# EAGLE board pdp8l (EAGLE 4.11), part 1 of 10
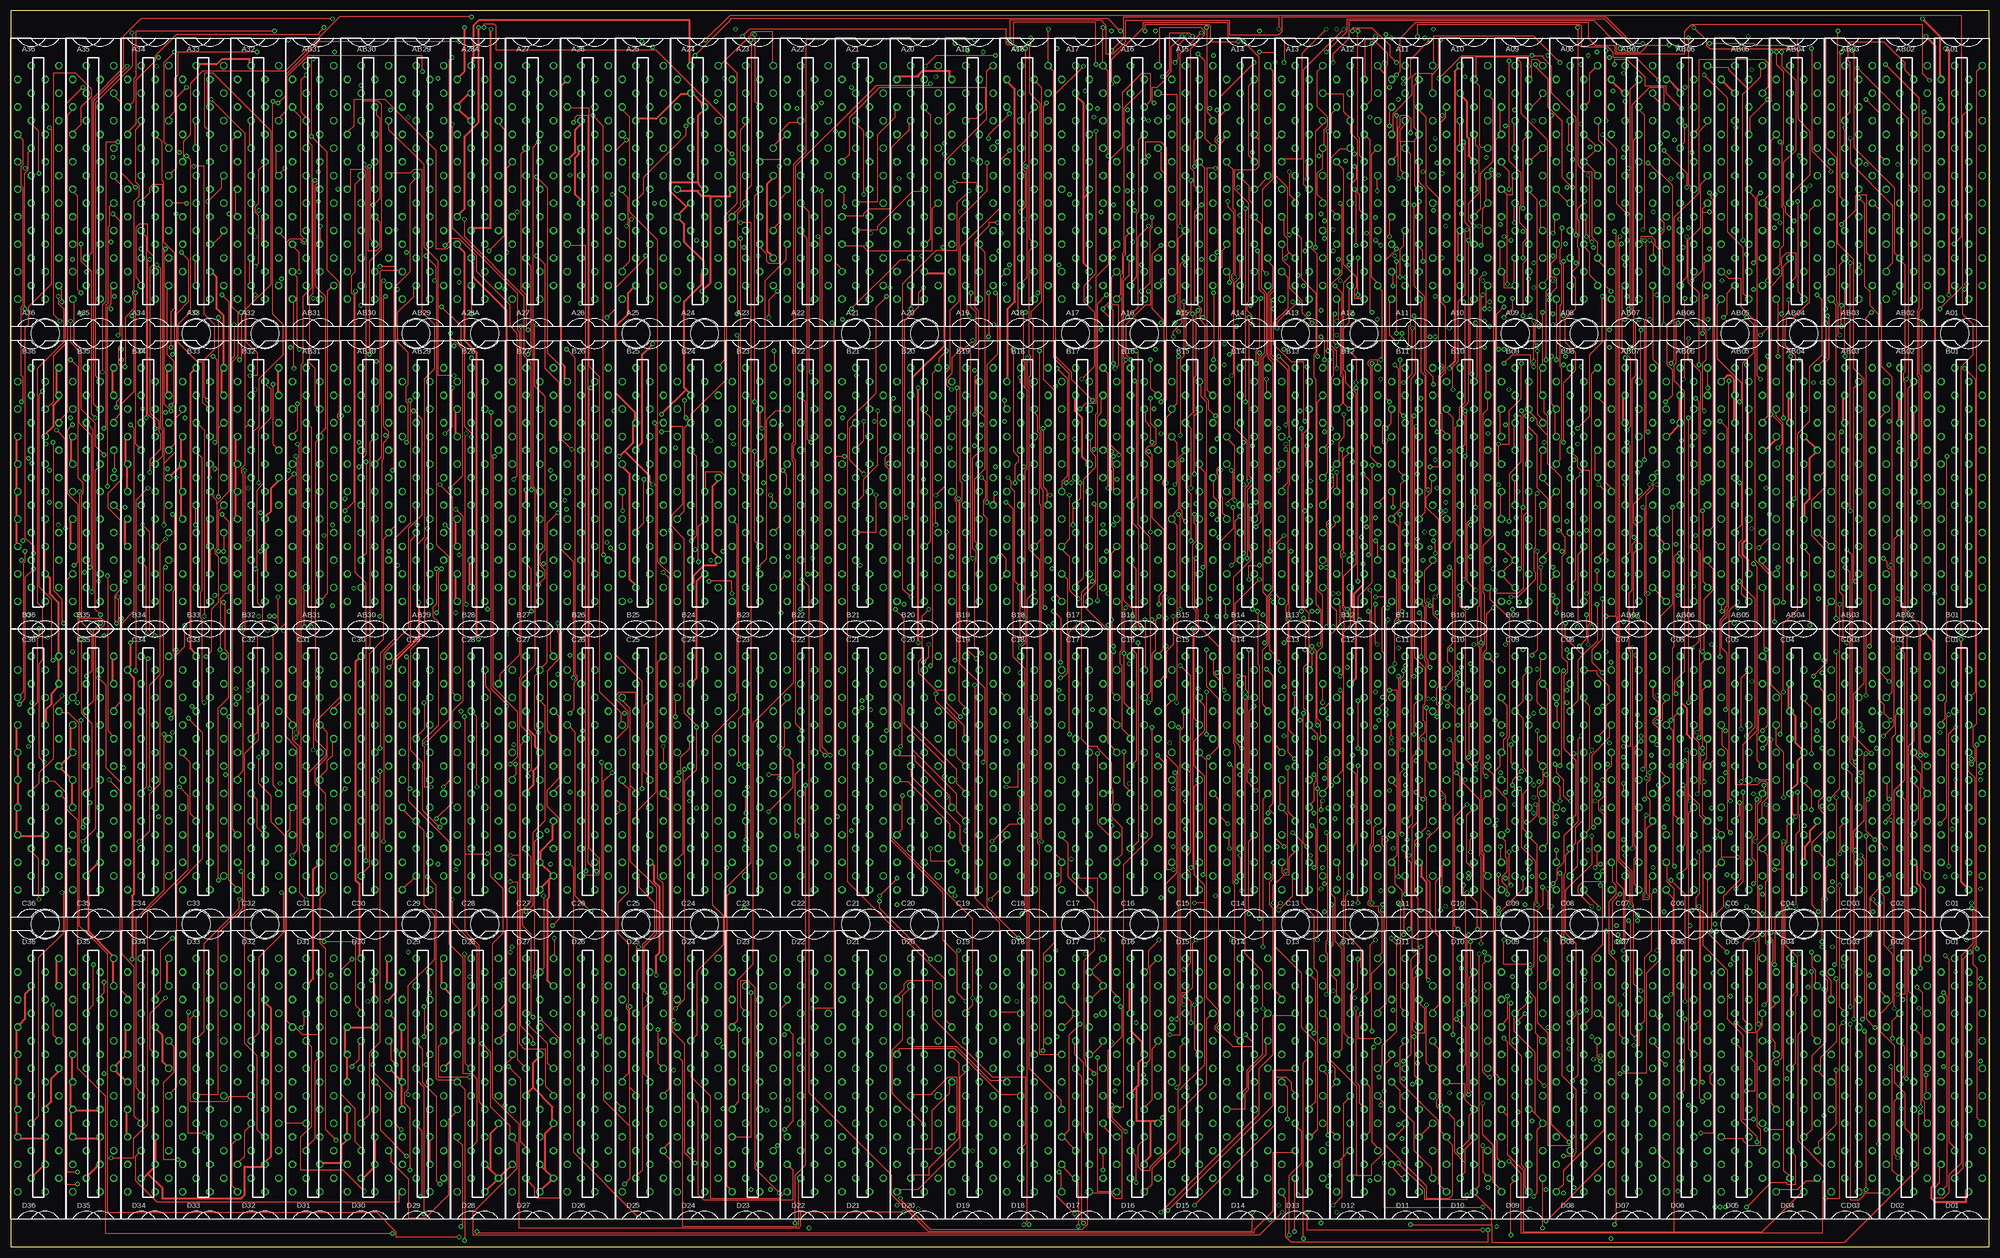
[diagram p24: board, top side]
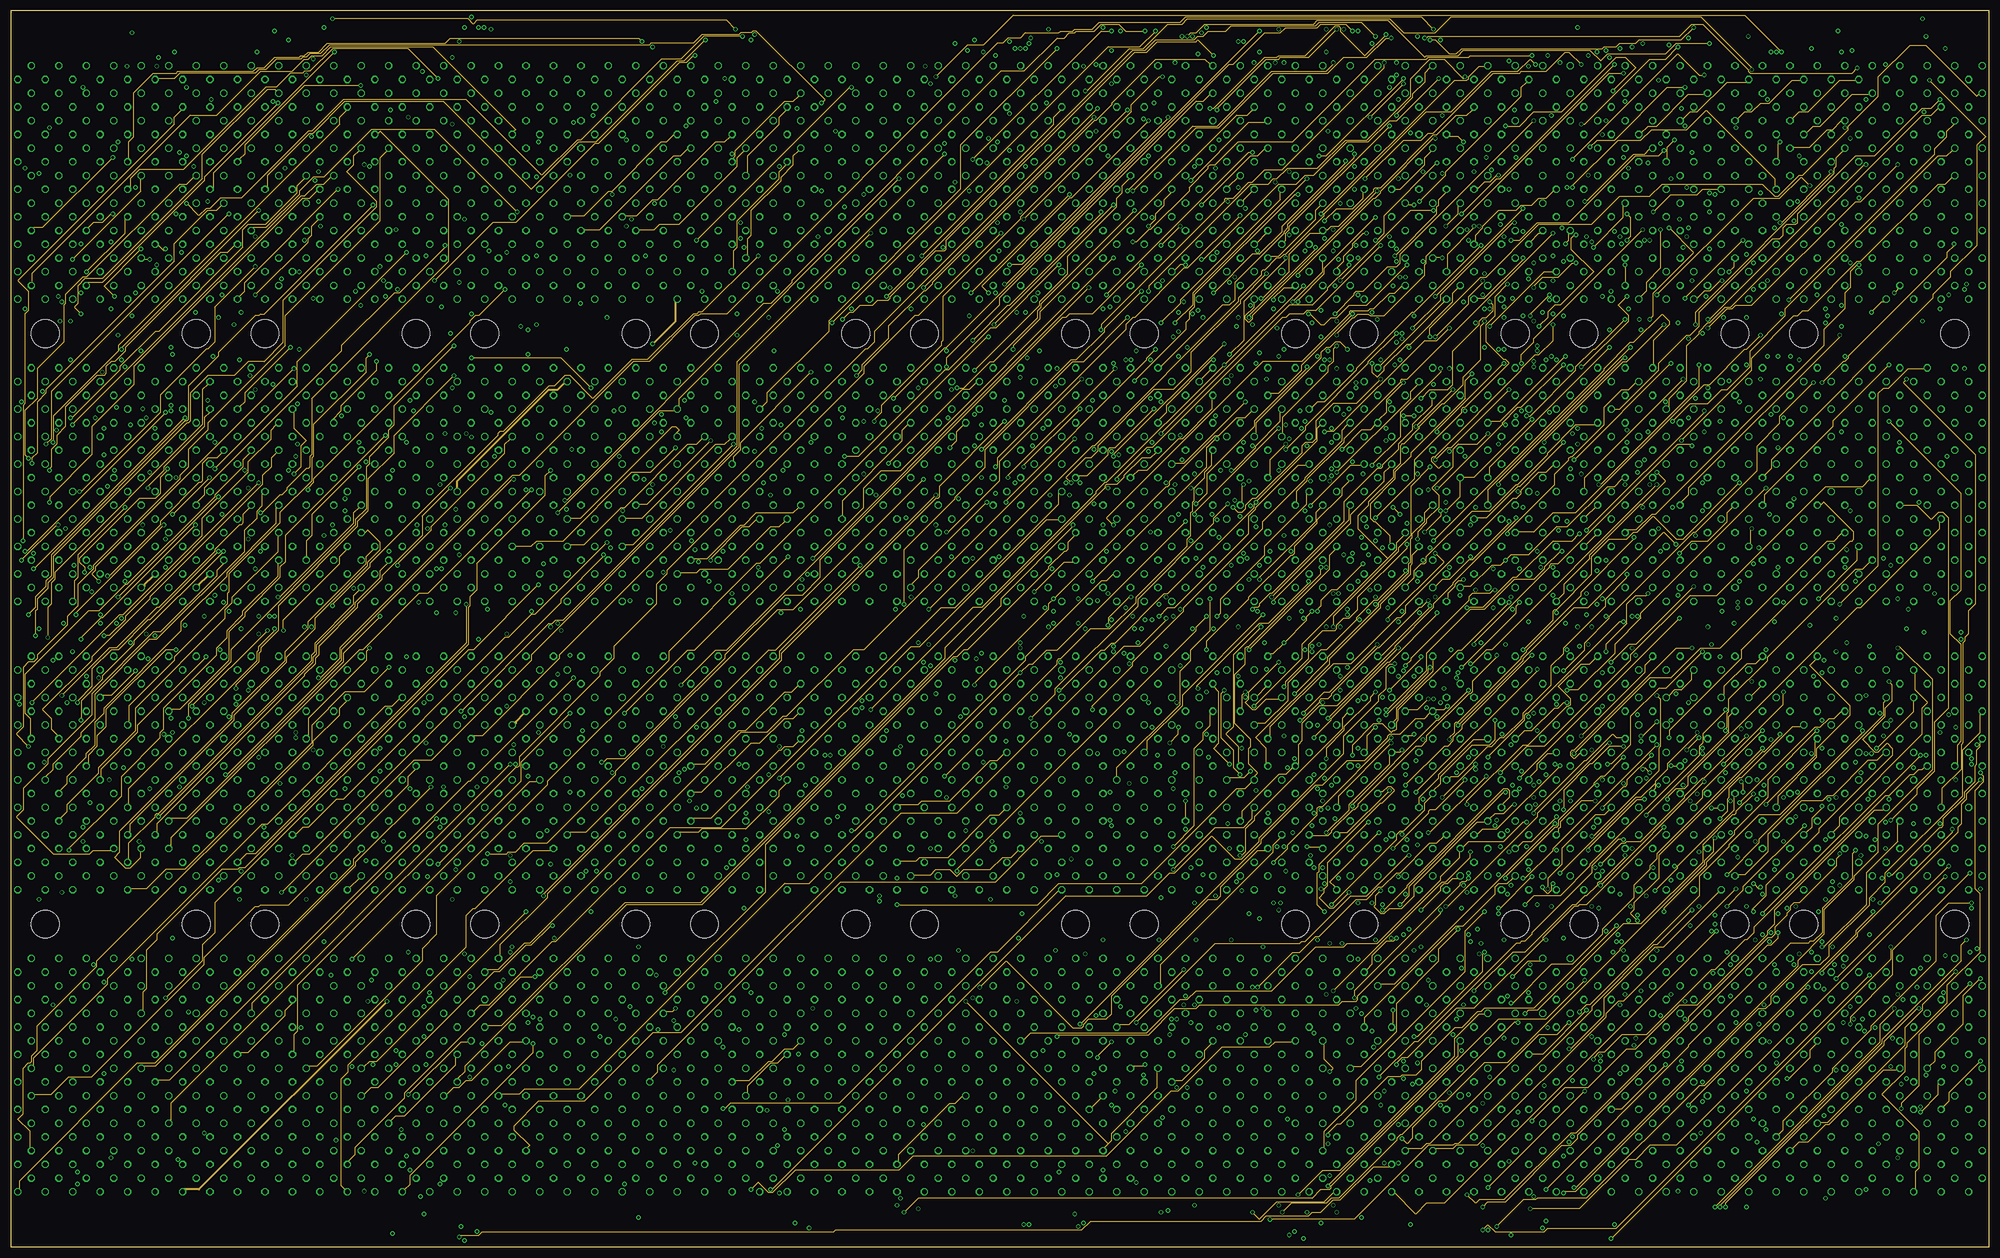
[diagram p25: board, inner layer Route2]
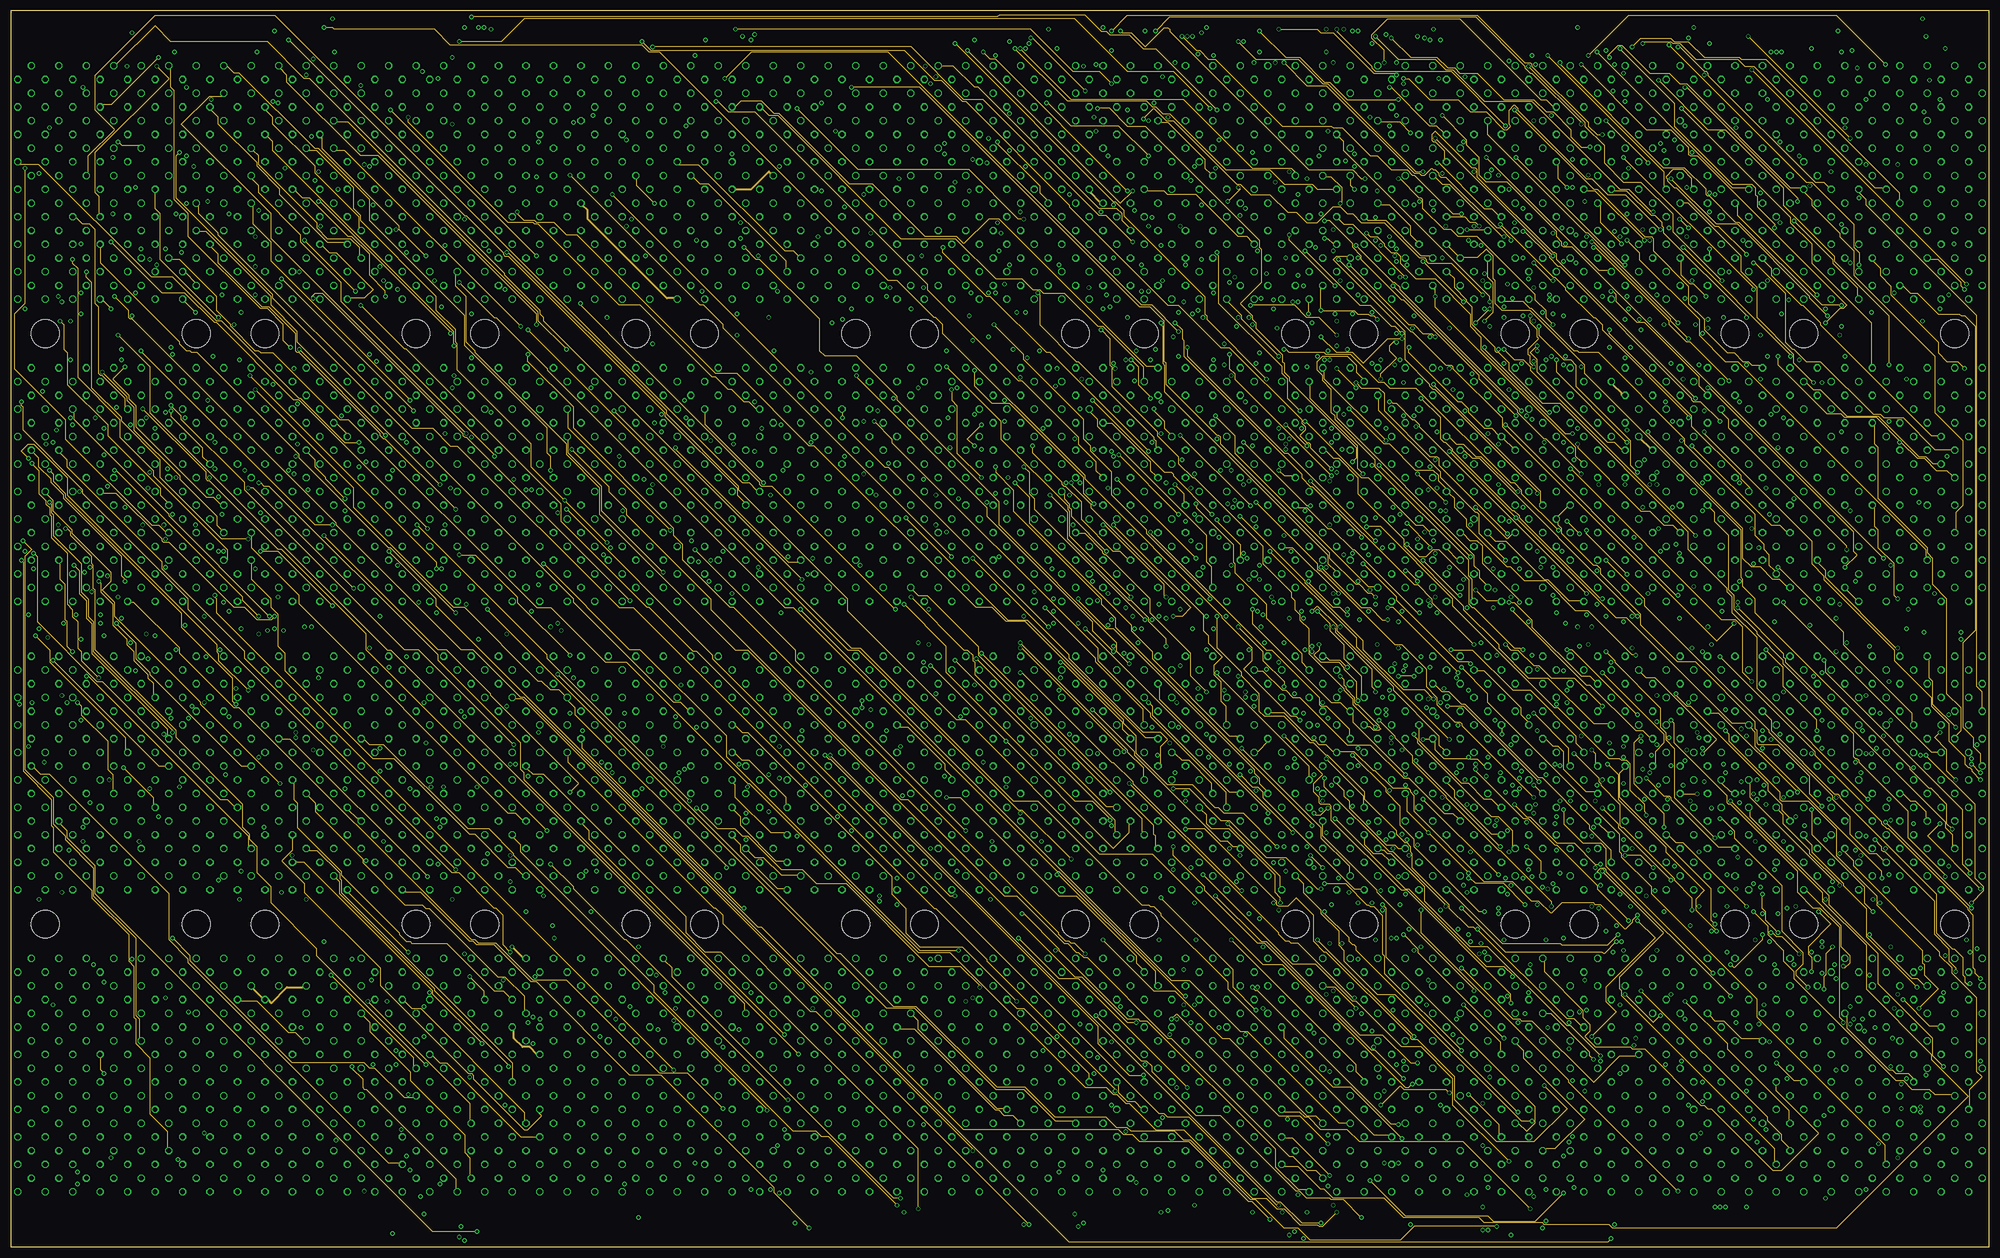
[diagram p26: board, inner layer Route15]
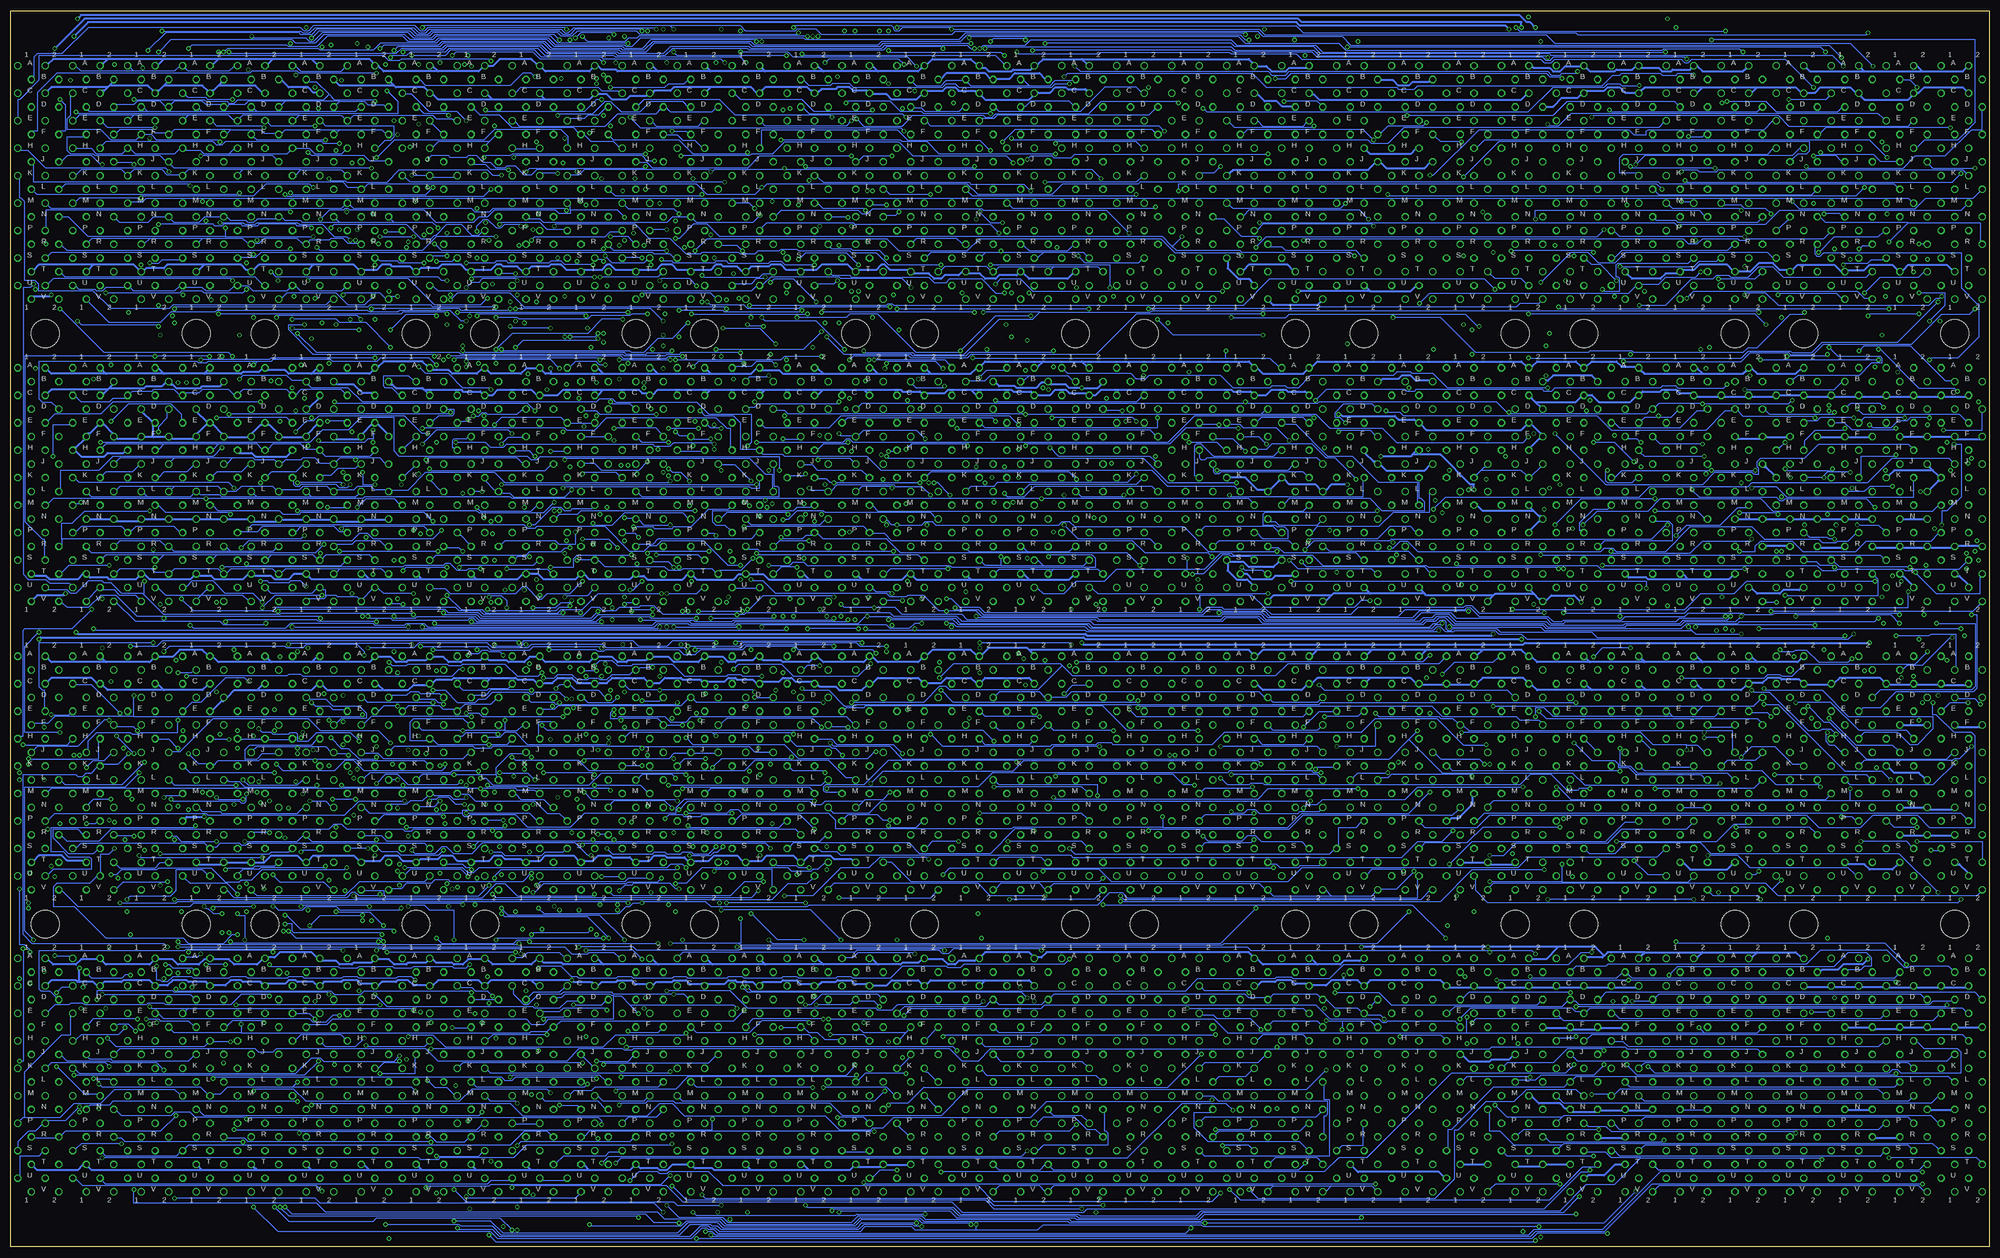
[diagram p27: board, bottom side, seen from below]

Size 457.2 x 285.75 mm. Coordinates in mm from the lower left corner, seen from the top.
Outline: 0,0 457.2,0 457.2,285.75 0,285.75 0,0
Copper layers (1*2*15*16): Top 0.035mm / dielectric 1.5mm / Route2 0.035mm / dielectric 0.15mm / Route15 0.035mm / dielectric 0.2mm / Bottom 0.035mm
Design rules "10mils": minimum track width 8mil, minimum drill 24mil, track to track 8mil, track to pad 8mil, pad to pad 8mil, via to via 8mil, smd to smd 8mil, copper to edge 25mil, drill to drill 8mil, minimum pad ring 8mil, minimum via ring 8mil, stop-mask expansion 0mil, vias tented up to drill 0mil, thermal gap 10mil
Net classes: 1 Supply: width 0.508 mm

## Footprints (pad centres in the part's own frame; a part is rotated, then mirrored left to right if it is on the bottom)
H807 = drill 1.092 octagon: A1 4.763,28.575; A2 -1.587,28.575; B1 1.587,25.4; B2 -4.763,25.4; C1 4.763,22.225; C2 -1.587,22.225; D1 1.587,19.05; D2 -4.763,19.05; E1 4.763,15.875; E2 -1.587,15.875; F1 1.587,12.7; F2 -4.763,12.7; H1 4.763,9.525; H2 -1.587,9.525; J1 1.587,6.35; J2 -4.763,6.35; K1 4.763,3.175; K2 -1.587,3.175; L1 1.587,0; L2 -4.763,0; M1 4.763,-3.175; M2 -1.587,-3.175; N1 1.587,-6.35; N2 -4.763,-6.35; P1 4.763,-9.525; P2 -1.587,-9.525; R1 1.587,-12.7; R2 -4.763,-12.7; S1 4.763,-15.875; S2 -1.587,-15.875; T1 1.587,-19.05; T2 -4.763,-19.05; U1 4.763,-22.225; U2 -1.587,-22.225; V1 1.587,-25.4; V2 -4.763,-25.4
H807-2 = drill 1.092 octagon: AA1 4.763,60.325; AA2 -1.587,60.325; AB1 1.587,57.15; AB2 -4.763,57.15; AC1 4.763,53.975; AC2 -1.587,53.975; AD1 1.587,50.8; AD2 -4.763,50.8; AE1 4.763,47.625; AE2 -1.587,47.625; AF1 1.587,44.45; AF2 -4.763,44.45; AH1 4.763,41.275; AH2 -1.587,41.275; AJ1 1.587,38.1; AJ2 -4.763,38.1; AK1 4.763,34.925; AK2 -1.587,34.925; AL1 1.587,31.75; AL2 -4.763,31.75; AM1 4.763,28.575; AM2 -1.587,28.575; AN1 1.587,25.4; AN2 -4.763,25.4; AP1 4.763,22.225; AP2 -1.587,22.225; AR1 1.587,19.05; AR2 -4.763,19.05; AS1 4.763,15.875; AS2 -1.587,15.875; AT1 1.587,12.7; AT2 -4.763,12.7; AU1 4.763,9.525; AU2 -1.587,9.525; AV1 1.587,6.35; AV2 -4.763,6.35; BA1 4.763,-9.525; BA2 -1.587,-9.525; BB1 1.587,-12.7; BB2 -4.763,-12.7; BC1 4.763,-15.875; BC2 -1.587,-15.875; BD1 1.587,-19.05; BD2 -4.763,-19.05; BE1 4.763,-22.225; BE2 -1.587,-22.225; BF1 1.587,-25.4; BF2 -4.763,-25.4; BH1 4.763,-28.575; BH2 -1.587,-28.575; BJ1 1.587,-31.75; BJ2 -4.763,-31.75; BK1 4.763,-34.925; BK2 -1.587,-34.925; BL1 1.587,-38.1; BL2 -4.763,-38.1; BM1 4.763,-41.275; BM2 -1.587,-41.275; BN1 1.587,-44.45; BN2 -4.763,-44.45; BP1 4.763,-47.625; BP2 -1.587,-47.625; BR1 1.587,-50.8; BR2 -4.763,-50.8; BS1 4.763,-53.975; BS2 -1.587,-53.975; BT1 1.587,-57.15; BT2 -4.763,-57.15; BU1 4.763,-60.325; BU2 -1.587,-60.325; BV1 1.587,-63.5; BV2 -4.763,-63.5
CBLOCK = hole 6.452: 7.938,68.263; 42.862,68.263

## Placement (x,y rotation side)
A01  G921  [H807]  450.85,244.47 0 top
A08  M617  [H807]  361.95,244.47 0 top
A09  M617  [H807]  349.25,244.47 0 top
A10  M160  [H807]  336.55,244.47 0 top
A11  M115  [H807]  323.85,244.47 0 top
A12  M160  [H807]  311.15,244.47 0 top
A13  M160  [H807]  298.45,244.47 0 top
A14  M115  [H807]  285.75,244.47 0 top
A15  M162  [H807]  273.05,244.47 0 top
A16  M162  [H807]  260.35,244.47 0 top
A17  G020  [H807]  247.65,244.47 0 top
A18  G020  [H807]  234.95,244.47 0 top
A19  G020  [H807]  222.25,244.47 0 top
A20  G020  [H807]  209.55,244.47 0 top
A21  W025A  [H807]  196.85,244.47 0 top
A22  W025A  [H807]  184.15,244.47 0 top
A23  G228  [H807]  171.45,244.47 0 top
A24  G228  [H807]  158.75,244.47 0 top
A25  G624  [H807]  146.05,244.47 0 top
A26  G624  [H807]  133.35,244.47 0 top
A27  G826A  [H807]  120.65,244.47 0 top
A28A  M916  [H807]  107.95,244.47 0 top
A32  M516  [H807]  57.15,244.47 0 top
A33  M516  [H807]  44.45,244.47 0 top
A34  M111  [H807]  31.75,244.47 0 top
A35  M111  [H807]  19.05,244.47 0 top
A36  M916  [H807]  6.35,244.47 0 top
AB02  M220  [H807-2]  438.15,212.72 0 top
AB03  M220  [H807-2]  425.45,212.72 0 top
AB04  M220  [H807-2]  412.75,212.72 0 top
AB05  M220  [H807-2]  400.05,212.72 0 top
AB06  M220  [H807-2]  387.35,212.72 0 top
AB07  M220  [H807-2]  374.65,212.72 0 top
AB29  M715  [H807-2]  95.25,212.72 0 top
AB30  M705  [H807-2]  82.55,212.72 0 top
AB31  M710  [H807-2]  69.85,212.72 0 top
B01  G921  [H807]  450.85,174.62 0 top
B08  M617  [H807]  361.95,174.62 0 top
B09  M617  [H807]  349.25,174.62 0 top
B10  M160  [H807]  336.55,174.62 0 top
B11  M216  [H807]  323.85,174.62 0 top
B12  M111  [H807]  311.15,174.62 0 top
B13  M113  [H807]  298.45,174.62 0 top
B14  M119  [H807]  285.75,174.62 0 top
B15  M119  [H807]  273.05,174.62 0 top
B16  M162  [H807]  260.35,174.62 0 top
B17  M162  [H807]  247.65,174.62 0 top
B18  G020  [H807]  234.95,174.62 0 top
B19  G020  [H807]  222.25,174.62 0 top
B20  G020  [H807]  209.55,174.62 0 top
B21  W025B  [H807]  196.85,174.62 0 top
B22  W025B  [H807]  184.15,174.62 0 top
B23  G228  [H807]  171.45,174.62 0 top
B24  G228  [H807]  158.75,174.62 0 top
B25  G624  [H807]  146.05,174.62 0 top
B26  G624  [H807]  133.35,174.62 0 top
B27  G826B  [H807]  120.65,174.62 0 top
B28  G785B  [H807]  107.95,174.62 0 top
B32  M906  [H807]  57.15,174.62 0 top
B33  M906  [H807]  44.45,174.62 0 top
B34  M903  [H807]  31.75,174.62 0 top
B35  M903  [H807]  19.05,174.62 0 top
B36  M903  [H807]  6.35,174.62 0 top
C01  G921  [H807]  450.85,107.95 0 top
C02  M113  [H807]  438.15,107.95 0 top
C04  M216  [H807]  412.75,107.95 0 top
C05  M113  [H807]  400.05,107.95 0 top
C06  M216  [H807]  387.35,107.95 0 top
C07  M111  [H807]  374.65,107.95 0 top
C08  M216  [H807]  361.95,107.95 0 top
C09  M115  [H807]  349.25,107.95 0 top
C10  M119  [H807]  336.55,107.95 0 top
C11  M117  [H807]  323.85,107.95 0 top
C12  M115  [H807]  311.15,107.95 0 top
C13  M117  [H807]  298.45,107.95 0 top
C14  M113  [H807]  285.75,107.95 0 top
C15  M113  [H807]  273.05,107.95 0 top
C16  M111  [H807]  260.35,107.95 0 top
C17  M360  [H807]  247.65,107.95 0 top
C18  G221  [H807]  234.95,107.95 0 top
C19  G221  [H807]  222.25,107.95 0 top
C20  G610A  [H807]  209.55,107.95 0 top
C21  H807  [H807]  196.85,107.95 0 top
C22  G610A  [H807]  184.15,107.95 0 top
C23  G221  [H807]  171.45,107.95 0 top
C24  G221  [H807]  158.75,107.95 0 top
C25  G228  [H807]  146.05,107.95 0 top
C26  M002  [H807]  133.35,107.95 0 top
C27  M623  [H807]  120.65,107.95 0 top
C28  M115  [H807]  107.95,107.95 0 top
C29  M660  [H807]  95.25,107.95 0 top
C30  M660  [H807]  82.55,107.95 0 top
C31  M916  [H807]  69.85,107.95 0 top
C32  M916  [H807]  57.15,107.95 0 top
C33  W023  [H807]  44.45,107.95 0 top
C34  M916  [H807]  31.75,107.95 0 top
C35  M903  [H807]  19.05,107.95 0 top
C36  M903  [H807]  6.35,107.95 0 top
CD03  M700  [H807-2]  425.45,76.2 0 top
D01  G921  [H807]  450.85,38.1 0 top
D02  M111  [H807]  438.15,38.1 0 top
D04  M115  [H807]  412.75,38.1 0 top
D05  M310  [H807]  400.05,38.1 0 top
D06  M310  [H807]  387.35,38.1 0 top
D07  M310  [H807]  374.65,38.1 0 top
D08  M310  [H807]  361.95,38.1 0 top
D09  M160  [H807]  349.25,38.1 0 top
D10  M216  [H807]  336.55,38.1 0 top
D11  M113  [H807]  323.85,38.1 0 top
D12  M113  [H807]  311.15,38.1 0 top
D13  M111  [H807]  298.45,38.1 0 top
D14  M310  [H807]  285.75,38.1 0 top
D15  M310  [H807]  273.05,38.1 0 top
D16  M216  [H807]  260.35,38.1 0 top
D17  M617  [H807]  247.65,38.1 0 top
D18  G221  [H807]  234.95,38.1 0 top
D19  G221  [H807]  222.25,38.1 0 top
D20  G611B  [H807]  209.55,38.1 0 top
D21  H807  [H807]  196.85,38.1 0 top
D22  G611B  [H807]  184.15,38.1 0 top
D23  G221  [H807]  171.45,38.1 0 top
D24  G221  [H807]  158.75,38.1 0 top
D25  G228  [H807]  146.05,38.1 0 top
D26  H807  [H807]  133.35,38.1 0 top
D27  M623  [H807]  120.65,38.1 0 top
D28  M623  [H807]  107.95,38.1 0 top
D29  M906  [H807]  95.25,38.1 0 top
D30  M906  [H807]  82.55,38.1 0 top
D31  M916  [H807]  69.85,38.1 0 top
D32  M916  [H807]  57.15,38.1 0 top
D33  W076  [H807]  44.45,38.1 0 top
D34  M903  [H807]  31.75,38.1 0 top
D35  M903  [H807]  19.05,38.1 0 top
D36  M903  [H807]  6.35,38.1 0 top
U$1  [CBLOCK]  0,6.35 0 top
U$2  [CBLOCK]  50.8,6.35 0 top
U$3  [CBLOCK]  101.6,6.35 0 top
U$4  [CBLOCK]  152.4,6.35 0 top
U$5  [CBLOCK]  203.2,6.35 0 top
U$6  [CBLOCK]  254,6.35 0 top
U$7  [CBLOCK]  304.8,6.35 0 top
U$8  [CBLOCK]  355.6,6.35 0 top
U$9  [CBLOCK]  406.4,6.35 0 top
U$10  [CBLOCK]  0,142.88 0 top
U$11  [CBLOCK]  50.8,142.88 0 top
U$12  [CBLOCK]  101.6,142.88 0 top
U$13  [CBLOCK]  152.4,142.88 0 top
U$14  [CBLOCK]  203.2,142.88 0 top
U$15  [CBLOCK]  254,142.88 0 top
U$16  [CBLOCK]  304.8,142.88 0 top
U$17  [CBLOCK]  355.6,142.88 0 top
U$18  [CBLOCK]  406.4,142.88 0 top

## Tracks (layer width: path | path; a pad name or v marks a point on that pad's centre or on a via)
3CYCLE  (via drill 0.61)
  Route15 0.203: v182.47,147.37 268.22,61.62 272.29,61.62 284.07,49.84 285.7,49.84 306.83,28.7 308.86,28.7 D12.P2 | v143.05,149.4 105.26,187.2 104.85,187.2 104.44,187.6 104.44,188.01 71.93,220.52 70.31,220.52 69.49,219.71 v69.9,219.3
  Bottom 0.203: v182.47,147.37 182.47,150.62 170.28,150.62 167.44,147.78 146.71,147.78 145.09,149.4 v143.05,149.4 | v69.9,219.3 68.28,220.93 30.48,220.93 28.85,219.3 27.64,219.3 A34.V2
(IOT+OPR)\  (via drill 0.61)
  Top 0.203: v314.55,49.84 314.55,63.25 317.4,66.09 317.4,77.47 v316.99,77.88
  Route2 0.203: v316.99,77.88 317.4,77.88 322.68,83.16 322.68,83.57 345.03,105.92 345.85,105.92 346.25,105.51 346.25,103.89 344.63,102.26 C09.N2
  Route15 0.203: C11.F1 325.53,120.14 325.53,116.89 335.28,107.14 336.91,107.14 340.56,103.48 342.19,103.48 343.81,101.85 C09.N2
  Bottom 0.203: v314.55,49.84 314.15,49.43 307.64,49.43 306.83,50.24 D12.F2
+3V(1)  (via drill 0.61)
  Top 0.203: C02.U1 442.57,86.41 441.76,87.22 441.76,103.48 442.57,104.29 C02.M1 442.57,105.51 441.76,106.32 441.76,112.01 440.13,113.64 C02.J1 | v418.59,121.77 419,122.17 419,128.27 417.78,129.49 C04.C1
  Bottom 0.203: v418.59,121.77 418.59,118.92 427.13,118.92 427.53,118.52 429.16,118.52 429.56,118.92 437.29,118.92 439.32,116.89 439.32,114.86 C02.J1
+3V(2)  (via drill 0.61)
  Top 0.203: C06.F2 383.24,120.14 384.05,119.33 384.05,111.61 v383.64,111.2 384.05,111.2 384.05,88.44 v384.45,88.04
  Route2 0.203: v383.64,111.2 385.27,111.2 C06.K2
  Bottom 0.203: C06.D1 388.52,126.64 384.45,126.64 382.83,125.02 376.73,125.02 375.11,123.39 375.11,122.17 380.8,122.17 382.02,120.95 C06.F2 | v384.45,88.04 384.86,87.63 399.49,87.63 399.9,87.22 403.56,87.22 404.37,86.41 C05.U1
+3V(3)  (via drill 0.61)
  Top 0.203: v357.23,125.42 357.23,121.36 C08.F2 | C08.D1 363.73,126.24 364.95,125.02 364.95,115.27 v365.35,114.86 365.35,114.45 364.95,114.05 364.95,96.57 364.13,95.76 C08.R1 363.32,94.54 362.1,93.32 362.1,88.04 360.48,86.41 C08.U2
  Route15 0.203: v365.35,114.86 366.17,114.05 366.17,111.61 C08.K1
  Bottom 0.203: v357.23,125.42 357.63,125.83 358.44,125.83 359.26,126.64 362.92,126.64 C08.D1 | C05.V1 401.12,81.94 400.3,81.13 379.98,81.13 376.73,84.38 361.7,84.38 360.88,85.19 C08.U2
+3V(4)  (via drill 0.61)
  Top 0.203: D11.L2 319.43,37.64 321.06,36.02 321.06,31.95 324.31,28.7 324.31,22.2 328.37,18.14 328.37,16.51 D11.U1 | 336.09,19.36 336.09,17.32 335.28,16.51 D10.U2 | 336.09,19.36 336.09,22.61 338.12,24.64 D10.R1 | 336.09,19.36 333.65,21.79 333.65,29.52 332.03,31.14 D10.N2 | v341.78,39.27 341.38,39.27 340.16,40.49 340.16,65.28 340.97,66.09 D10.A1
  Bottom 0.203: D11.A1 329.18,66.9 330.4,68.12 337.72,68.12 338.94,66.9 340.56,66.9 D10.A1 | D10.U2 334.47,15.29 329.18,15.29 D11.U1 | v341.78,39.27 341.38,39.68 321.06,39.68 319.84,38.46 D11.L2
+3V(5)
  Top 0.203: C10.U1 340.97,86.41 340.56,86.82 340.56,90.88 340.16,91.29 340.16,103.48 340.97,104.29 C10.M1 | C10.F2 331.22,120.14 330.4,119.33 330.4,105.51 331.62,104.29 331.62,102.26 C10.N2
  Bottom 0.203: C10.H2 335.28,118.11 335.28,121.36 332.03,121.36 C10.F2 | C10.N2 332.44,101.85 334.06,103.48 339.34,103.48 340.56,104.7 C10.M1
+3V(6)
  Top 0.203: A10.E2 334.87,259.54 334.87,254.66 A10.H2 | A09.U1 354.38,222.96 355.19,223.77 355.19,255.88 349.1,261.98 349.1,273.76 347.88,274.98 338.53,274.98 338.53,270.51 A10.B1 338.53,269.29 339.34,268.48 339.34,254.66 339.75,254.25 340.56,254.25 A10.H1
  Bottom 0.203: A10.H2 335.69,253.85 340.56,253.85 A10.H1
+3V(7)  (via drill 0.61)
  Top 0.203: B10.R2 332.44,162.41 333.25,163.22 333.25,191.67 332.03,192.89 B10.D2 | v353.57,157.12 353.57,153.06 B09.U1
  Route15 0.203: B10.S2 334.47,159.16 334.06,159.16 332.03,161.19 B10.R2
  Bottom 0.203: v353.57,157.12 353.16,157.53 336.5,157.53 335.69,158.34 B10.S2
+3V(8)  (via drill 0.61)
  Top 0.203: D09.D1 350.32,56.74 350.32,56.34 348.29,54.3 D09.E2 347.47,53.49 347.47,49.84 352.35,44.96 352.35,30.73 | v351.94,11.63 352.75,12.45 352.75,27.08 353.57,27.89 D09.P1 353.57,29.11 353.57,29.52 352.35,30.73 | 352.35,30.73 351.54,31.55 D09.N1
  Bottom 0.203: D09.D2 345.03,57.15 350.32,57.15 D09.D1 | v351.94,11.63 351.54,11.23 326.75,11.23 325.93,12.04 D11.V1
+3V(9)  (via drill 0.61)
  Top 0.203: A12.N2 306.02,238.81 305.21,239.62 305.21,251.82 307.24,253.85 308.86,253.85 A12.H2 | v350.72,223.77 350.72,219.71 A09.V1
  Route15 0.203: v322.27,224.18 310.08,236.37 308.05,236.37 306.83,237.59 A12.N2
  Bottom 0.203: v350.72,223.77 350.32,224.18 v322.27,224.18
+3V(10)  (via drill 0.61)
  Top 0.203: v366.57,156.31 366.57,153.06 B08.U1 | v356.41,157.12 356.01,157.53 356.01,173.38 356.82,174.19 B08.L2
  Bottom 0.203: v366.57,156.31 365.76,157.12 v356.41,157.12 | B08.K2 360.07,177.04 358.04,175.01 357.63,175.01 B08.L2
+3V(11)  (via drill 0.61)
  Top 0.203: v319.84,203.86 320.65,203.05 320.65,179.48 321.87,178.26 B11.K2 321.87,177.04 321.06,176.22 321.06,170.54 319.43,168.91 B11.N2 319.43,167.69 320.65,166.47 v320.65,144.53 | v350.72,144.53 350.72,148.59 B09.V1
  Bottom 0.203: v319.84,203.86 321.06,203.86 321.87,204.67 326.75,204.67 327.96,203.45 B11.A1 | v350.72,144.53 350.32,144.12 321.06,144.12 v320.65,144.53
+3V(12)
  Top 0.203: B10.P1 340.97,165.66 340.16,166.47 340.16,192.48 341.38,193.7 341.38,196.14 B10.C1 340.97,197.36 340.97,202.64 B10.A1
  Route15 0.203: B08.V1 362.92,149.4 360.07,149.4 355.19,154.28 354.38,154.28 345.44,163.22 343,163.22 341.78,164.44 B10.P1
+3V(13)  (via drill 0.61)
  Top 0.203: v256.44,55.52 256.85,55.12 256.85,48.62 253.59,45.36 253.59,29.92 256.85,26.67 256.85,11.23 255.22,11.23 254.41,12.04 254.41,12.45 249.94,12.45 D17.V1 249.12,12.04 248.72,11.63 248.72,5.13 247.5,3.91 212.55,3.91 205.64,10.82 v205.64,11.23 | D25.A1 150.77,67.31 150.77,83.97 149.56,85.19 149.56,135.18 150.37,135.99 C25.A1 | v286.11,77.06 286.11,93.73 286.92,94.54 C14.R1 | v273.91,70.97 273.1,70.16 273.1,60 271.88,58.78 270.66,58.78 270.66,56.34 v271.07,55.93
  Route15 0.203: v205.64,11.23 204.01,11.23 152.81,62.43 152.81,64.47 151.18,66.09 D25.A1
  Bottom 0.203: v256.44,55.52 257.66,56.74 261.31,56.74 D16.D1 262.53,56.74 263.35,55.93 v271.07,55.93 | v286.11,77.06 280.01,70.97 v273.91,70.97
+3V(15)
  Top 0.203: D31.S2 68.28,23.01 70.31,25.04 70.31,42.93 71.12,43.74 D31.J1 71.12,44.96 71.12,49.02 67.46,49.02 65.84,50.65 D31.F2 64.62,51.46 63.8,52.27 63.8,95.76 64.62,96.57 64.62,101.04 C31.N2
  Bottom 0.203: C31.N2 65.84,101.45 70.71,101.45 C31.N1
+3V(16)
  Top 0.203: D32.R1 58.12,25.86 56.9,27.08 56.9,44.15 54.05,46.99 54.05,114.05 57.3,117.3 57.3,125.02 58.52,126.24 C32.D1
+3V(17)
  Bottom 0.203: B14.U2 284.89,152.25 289.76,152.25 B14.U1
+3V(18)
  Top 0.203: A08.U1 366.57,222.96 364.95,224.59 364.95,229.87 363.73,231.09 A08.R1
-15V  (via drill 0.61)
  Top 0.508: v28.04,66.5 28.04,81.13 28.45,81.53 28.45,131.52 27.23,132.74 C34.B2 27.23,133.96 27.64,134.37 v27.64,139.65 | A20.B2 205.23,270.51 209.7,270.51 209.7,270.92 210.51,271.73 217.02,271.73 217.02,270.51 A19.B2 | B18.B2 230.43,200.61 230.43,216.86 232.05,218.49 232.05,267.67 230.43,269.29 A18.B2 | v209.7,139.65 v209.7,198.58
  Bottom 0.508: v28.04,66.5 29.26,65.28 33.73,65.28 34.95,64.06 38.61,64.06 39.01,63.65 D33.B2 | B20.B2 205.23,199.39 206.04,198.58 v209.7,198.58 212.55,198.58 213.36,199.39 217.02,199.39 B19.B2 218.24,199.8 219.05,199.8 220.27,198.58 224.74,198.58 225.15,198.98 228.8,198.98 229.62,199.8 B18.B2 | A17.B2 242.21,270.1 241,271.32 232.05,271.32 230.84,270.1 A18.B2 229.62,270.1 226.37,270.1 225.15,271.32 219.46,271.32 218.24,270.1 A19.B2 | v27.64,139.65 107.29,139.65 107.7,139.24 209.3,139.24 v209.7,139.65
A  (via drill 0.61)
  Route2 0.203: v34.14,99.42 69.9,135.18 69.9,136.4 70.71,137.21 70.71,139.24 79.65,148.18 79.65,149 85.34,154.69 85.34,156.31 86.97,157.94 AB30.BS1
  Bottom 0.203: v34.14,99.42 31.7,99.42 30.89,98.6 C34.P2
A01B2  (via drill 0.61)
  Top 0.508: v104.85,281.89 104.85,271.73 103.63,270.51 A28A.B2 | v441.76,283.92 445.82,279.86 445.82,270.51 A01.B2
  Bottom 0.508: v104.85,281.89 106.07,283.11 106.88,283.11 108.51,284.73 440.94,284.73 v441.76,283.92
A01V1  (via drill 0.61)
  Top 0.508: v108.1,281.89 108.1,259.94 104.85,256.69 104.85,240.03 103.63,238.81 A28A.N2 | v447.04,277.01 447.85,276.2 v447.85,220.12
  Bottom 0.508: v108.1,281.89 108.1,283.11 158.9,283.11 159.72,283.92 440.13,283.92 v447.04,277.01 | v447.85,220.12 448.26,219.71 451.92,219.71 A01.V1
A\
  Route2 0.203: C34.R2 27.64,95.76 27.64,97.79 51.61,121.77 51.61,122.99 63.8,135.18 63.8,136.4 70.31,142.9 70.31,145.34 82.5,157.53 82.5,158.34 85.34,161.19 85.34,162.81 82.5,165.66 81.69,164.85 AB30.BP2
AC00  (via drill 0.61)
  Top 0.203: v125.58,71.37 125.58,67.31 D27.A1 | v328.78,163.22 329.18,162.81 v329.18,160.38
  Route2 0.203: v204.83,79.1 237.34,79.1 242.21,83.97 261.31,83.97 283.26,105.92 285.29,105.92 286.92,107.54 C14.L1 287.32,108.76 288.14,109.58 286.11,111.61 286.11,115.27 286.51,115.67 286.51,117.3 282.85,120.95 282.85,132.33 285.29,134.77 285.29,138.43 285.7,138.84 286.11,138.84 302.77,155.5 v302.77,157.12 | v328.78,163.22 368.2,202.64 368.2,203.05 374.29,209.14 375.11,209.14 381.61,215.65 383.24,214.02 383.24,213.21 379.58,209.55 379.58,203.86 AB07.BA1 | v329.18,160.38 331.22,158.34 318.21,145.34 v318.21,144.93
  Route15 0.203: v318.21,144.93 316.99,144.93 314.15,147.78 312.12,147.78 v302.77,157.12
  Bottom 0.203: v125.58,71.37 133.3,79.1 v204.83,79.1
AC00\  (via drill 0.61)
  Top 0.203: v308.86,207.52 310.9,205.49 v310.9,199.8 | v376.73,211.99 376.73,200.61 AB07.BB1
  Route2 0.203: v308.86,207.52 307.24,209.14 306.02,209.14 304.8,207.92 303.99,207.92 302.77,206.7 302.77,205.49 287.73,190.45 287.73,188.01 B14.F1 | v345.85,164.85 345.85,165.25 356.82,176.22 356.82,178.66 360.07,181.91 360.07,182.32 360.48,182.73 360.88,182.73 368.2,190.04 368.2,194.11 372.26,198.17 373.89,198.17 375.51,199.8 AB07.BB1 | v436.07,250.19 427.53,241.66 426.31,241.66 402.34,217.68 398.68,217.68 397.87,216.86 396.65,216.86 v392.18,212.39
  Route15 0.203: v310.9,199.8 312.12,198.58 316.18,198.58 317.4,197.36 317.4,193.29 327.96,182.73 329.59,182.73 330,182.32 330,180.7 v345.85,164.85
  Bottom 0.203: v436.07,250.19 436.47,250.19 438.51,252.22 444.19,252.22 445.41,251 A01.J2 | v392.18,212.39 391.77,211.99 v376.73,211.99
AC01  (via drill 0.61)
  Top 0.203: v123.14,81.13 123.14,64.47 122.73,64.06 D27.B1 | v213.77,173.79 215.8,175.82 215.8,201.83 217.02,203.05 217.02,216.46 219.05,218.49 219.05,237.59 225.55,244.09 v225.55,250.6
  Route2 0.203: v123.14,81.13 123.14,81.53 177.6,135.99 177.6,137.62 v213.77,173.79 | v302.36,252.22 303.99,252.22 v321.87,270.1 | v381.2,235.15 381.2,226.21 377.95,222.96 377.95,220.93 376.73,219.71 AB07.AV1
  Route15 0.203: v321.87,270.1 323.09,270.1 327.96,265.23 334.47,265.23 337.31,262.38 340.97,262.38 345.03,258.32 345.85,258.32 346.66,259.13 346.25,259.54 346.25,262.79 347.47,264.01 348.29,263.2 348.29,262.79 364.13,246.94 365.35,246.94 369.01,243.28 373.07,243.28 v381.2,235.15
  Bottom 0.203: v225.55,250.6 227.18,252.22 248.72,252.22 251.97,255.47 278.38,255.47 281.23,252.63 286.11,252.63 286.51,252.22 v302.36,252.22
AC01\  (via drill 0.61)
  Top 0.203: v362.1,189.23 364.95,192.07 364.95,206.3 367.79,209.14 v367.79,219.71
  Route2 0.203: v415.75,245.31 413.71,247.34 408.84,242.47 402.74,242.47 v380.39,220.12
  Bottom 0.203: v362.1,189.23 329.18,189.23 328.78,188.82 322.27,188.82 319.43,191.67 294.23,191.67 291.8,189.23 290.98,189.23 290.98,184.76 B14.H1 | v367.79,219.71 369.42,219.71 AB07.AV2 370.64,219.3 371.86,220.52 379.98,220.52 v380.39,220.12 | v415.75,245.31 416.15,245.72 444.6,245.72 445.41,244.91 A01.L2
AC02  (via drill 0.61)
  Top 0.203: v427.53,109.58 425.09,112.01 425.09,155.91 v423.88,157.12 | v392.18,198.58 392.18,202.64 AB06.BA1
  Route2 0.203: v395.02,9.2 395.02,9.6 432.41,46.99 432.41,47.8 450.7,66.09 450.7,69.75 v451.92,70.97
  Route15 0.203: v250.75,53.49 261.31,42.93 262.53,42.93 263.75,41.71 263.75,40.49 273.91,30.33 279.6,30.33 297.08,12.85 297.89,12.85 299.52,11.23 304.8,11.23 305.21,10.82 308.05,10.82 v312.12,6.76 | v423.88,157.12 426.72,159.97 425.91,160.78 425.91,165.25 392.58,198.58 v392.18,198.58
  Bottom 0.203: v250.75,53.49 249.12,55.12 219.05,55.12 218.24,55.93 155.65,55.93 152.4,52.68 141.02,52.68 140.21,51.87 139.4,51.87 138.99,52.27 123.55,52.27 122.73,51.46 D27.F1 | v312.12,6.76 312.52,7.16 392.99,7.16 v395.02,9.2 | v451.92,70.97 453.95,73 453.95,106.32 430.78,106.32 v427.53,109.58
AC02\  (via drill 0.61)
  Top 0.203: v286.92,185.17 286.92,181.51 B14.J1 | v404.37,243.69 403.56,242.88 403.56,201.42 v404.37,200.61
  Bottom 0.203: v286.92,185.17 286.11,185.98 286.11,192.48 295.86,192.48 298.7,195.33 317.4,195.33 318.21,196.14 321.06,196.14 321.87,195.33 375.92,195.33 379.17,198.58 387.71,198.58 388.52,199.39 AB06.BB1 389.74,200.2 392.18,200.2 393.39,201.42 403.56,201.42 v404.37,200.61 | v404.37,243.69 404.77,243.28 451.1,243.28 451.92,244.09 A01.L1
AC03  (via drill 0.61)
  Top 0.203: v136.14,48.62 136.55,49.02 v136.55,112.01 | v330,270.1 335.28,275.39 350.72,275.39 v350.72,272.95
  Route2 0.203: v136.55,112.01 136.96,112.01 137.77,112.83 141.83,112.83 165,135.99 165,136.8 178.82,150.62 182.88,150.62 186.94,154.69 186.94,158.75 243.03,214.83 243.84,214.83 244.65,215.65 249.94,215.65 v261.31,227.03 | v275.13,228.24 275.54,228.24 293.01,245.72 297.08,245.72 299.11,247.75 301.14,247.75 308.86,255.47 313.74,255.47 318.62,260.35 320.24,260.35 v330,270.1 | v395.43,223.37 395.02,223.37 392.58,220.93 391.36,220.93 389.74,219.3 AB06.AV1
  Route15 0.203: v350.72,272.95 363.73,259.94 363.73,259.13 368.2,254.66 368.2,250.6 372.67,246.13 376.73,246.13 384.05,238.81 384.05,234.75 v395.43,223.37
  Bottom 0.203: v136.14,48.62 135.74,49.02 126.8,49.02 125.98,48.21 D27.H1 | v261.31,227.03 264.16,229.87 273.51,229.87 v275.13,228.24
AC03\  (via drill 0.61)
  Top 0.203: v382.02,213.21 382.02,218.49 AB06.AV2
  Route2 0.203: v294.64,185.57 290.98,181.91 290.98,178.26 B14.K1 | v354.38,185.98 354.38,186.38 372.67,204.67 373.48,204.67 v382.02,213.21
  Bottom 0.203: v294.64,185.57 295.05,185.98 303.99,185.98 304.8,185.17 308.46,185.17 308.86,185.57 342.6,185.57 343.41,184.76 346.25,184.76 347.47,185.98 v354.38,185.98 | A01.K1 455.17,246.94 455.17,242.47 454.76,242.47 453.95,241.66 453.95,223.37 451.51,223.37 450.7,222.56 450.7,220.93 438.1,220.93 434.04,216.86 420.62,216.86 419.81,217.68 384.45,217.68 383.24,218.9 AB06.AV2
AC04  (via drill 0.61)
  Top 0.203: 117.45,90.47 v115.42,90.47 | 117.45,90.47 117.45,46.99 118.67,45.77 123.55,45.77 123.55,37.24 125.17,35.61 D27.M1 | v117.86,212.8 117.86,131.93 117.45,131.52 117.45,90.47 | v177.19,220.93 175.16,218.9 v175.16,214.83
  Route2 0.203: v288.54,281.08 230.02,222.56 v229.62,222.56
  Route15 0.203: v117.86,212.8 77.22,253.44 75.18,253.44 AB31.AH1 | v347.47,262.79 365.76,244.5 366.57,244.5 377.55,233.53 379.17,233.53 379.58,233.12 379.58,230.28 387.71,222.15 387.71,218.08 391.36,214.43 391.36,211.99 396.65,206.7 398.27,206.7 400.3,204.67 401.52,204.67 402.34,203.86 404.37,203.86 AB05.BA1 | v320.65,265.23 308.86,265.23 304.8,269.29 303.58,269.29 297.89,274.98 294.64,274.98 v288.54,281.08
  Bottom 0.203: v115.42,90.47 112.17,90.47 109.32,93.32 88.19,93.32 84.94,96.57 69.9,96.57 68.68,97.79 C31.P2 | v347.47,262.79 347.07,262.38 324.71,262.38 321.87,265.23 v320.65,265.23 | v229.62,222.56 228.4,223.77 223.93,223.77 221.08,220.93 v177.19,220.93 | v175.16,214.83 162.56,214.83 161.75,215.65 121.11,215.65 118.26,212.8 v117.86,212.8
AC04\  (via drill 0.61)
  Top 0.203: v401.12,203.86 401.12,200.61 AB05.BB1
  Route2 0.203: v329.59,175.41 330,175.41 344.63,190.04 344.63,190.45 348.29,194.11 349.1,194.11 v358.85,203.86
  Bottom 0.203: v329.59,175.41 329.18,175.82 286.51,175.82 286.11,175.41 284.07,175.41 284.07,177.04 B14.K2 | v358.85,203.86 360.48,205.49 371.86,205.49 372.67,204.67 382.83,204.67 383.24,205.08 396.65,205.08 397.05,204.67 400.3,204.67 | 400.3,204.67 v401.12,203.86 | 400.3,204.67 411.68,204.67 412.09,204.27 413.71,204.27 414.12,204.67 450.7,204.67 450.7,196.14 449.88,195.33 447.85,195.33 446.63,194.11 B01.D2
AC05  (via drill 0.61)
  Top 0.203: v391.36,270.92 396.65,265.63 396.65,234.75 400.3,231.09 400.3,220.52 401.12,219.71 AB05.AV1 | v283.67,278.64 277.17,278.64 277.17,282.3 276.76,282.7 262.13,282.7 v262.13,281.08
  Route2 0.203: v137.77,162.81 121.11,146.15 120.29,146.15 115.01,140.87 114.2,140.87 76.81,103.48 75.18,103.48 68.68,96.98 67.46,96.98 65.84,95.35 C31.R2 | v391.36,270.92 390.14,270.92 385.27,275.79 v360.88,251.41 | v262.13,281.08 257.66,281.08 256.03,282.7 251.97,282.7 250.34,281.08 246.28,281.08 245.87,280.67 244.65,280.67 243.43,279.45 241.81,279.45 234.09,271.73 228.8,271.73 180.44,223.37 180.44,222.96 175.56,218.08 173.94,218.08 128.42,172.57 v128.02,172.57
  Route15 0.203: C31.R2 65.02,94.54 65.02,91.69 62.59,89.26 67.87,83.97 67.87,81.94 85.34,64.47 85.34,60.4 105.66,40.08 106.48,40.08 106.88,39.68 106.88,38.86 118.67,27.08 119.48,27.08 122.73,30.33 121.92,31.14 D27.N1 | v137.77,162.81 v128.02,172.57 120.29,180.29 120.29,185.57 103.23,202.64 103.23,208.74 102.82,209.14 102.82,211.99 98.35,216.46 98.35,219.71 80.87,237.19 80.87,238.4 79.25,240.03 79.25,244.91 70.71,253.44 68.68,253.44 AB31.AH2 | v326.34,248.56 324.71,248.56 304.39,268.88 303.17,268.88 297.49,274.57 287.73,274.57 v283.67,278.64
  Bottom 0.203: v360.88,251.41 360.07,252.22 356.01,252.22 355.6,251.82 351.94,251.82 351.54,252.22 349.5,252.22 347.88,250.6 346.25,250.6 345.03,249.38 343,249.38 342.6,249.78 340.56,249.78 338.53,247.75 336.91,247.75 335.69,248.97 326.75,248.97 v326.34,248.56
AC05\  (via drill 0.61)
  Top 0.203: v399.49,195.33 399.9,195.73 399.9,199.8 394.21,205.49 394.21,217.68 395.02,218.49 AB05.AV2
  Route2 0.203: v329.18,181.91 332.03,184.76 332.84,184.76 v346.25,198.17 | v362.92,203.45 363.32,203.45 373.89,214.02 373.89,215.24 371.45,217.68 v373.48,219.71
  Bottom 0.203: v329.18,181.91 328.78,182.32 286.51,182.32 282.85,178.66 281.23,178.66 281.23,175.41 B14.L2 | v346.25,198.17 346.66,198.58 352.75,198.58 356.01,201.83 361.29,201.83 v362.92,203.45 | v373.48,219.71 375.51,217.68 379.17,217.68 382.02,220.52 393.39,220.52 394.61,219.3 AB05.AV2 | v399.49,195.33 433.63,195.33 436.47,192.48 447.04,192.48 448.67,190.86 B01.E2
AC06  (via drill 0.61)
  Top 0.203: v95.91,229.06 98.35,226.62 98.35,223.37 | 98.35,223.37 98.35,162.41 101.19,159.56 101.19,121.77 v95.91,116.48 | v419.4,213.61 419.4,205.49 417.78,203.86 AB04.BA1 | v256.44,281.08 253.59,283.92 166.22,283.92 166.22,283.52 v158.09,275.39 | v97.94,223.37 98.35,223.37
  Route2 0.203: v362.92,273.36 360.07,276.2 359.26,276.2 354.79,271.73 349.1,271.73 348.69,271.32 342.6,271.32 328.78,257.5 327.56,257.5 325.93,255.88 321.87,255.88 v312.93,246.94 | v158.09,275.39 157.68,275.39 156.06,273.76 154.43,273.76 135.74,255.07 134.93,255.07 116.64,236.78 111.35,236.78 v97.94,223.37
  Route15 0.203: C31.L2 65.43,107.14 65.43,103.48 66.24,102.67 66.24,96.98 76.4,86.82 76.4,86 89.81,72.59 89.81,72.19 91.44,70.56 92.25,70.56 92.66,70.16 100.79,70.16 111.76,59.18 113.79,59.18 115.42,57.56 D27.D2 | v95.91,229.06 89.81,235.15 89.81,235.97 71.93,253.85 71.93,256.69 AB31.AF1 | v419.4,213.61 422.66,216.86 423.47,216.86 424.28,217.68 389.74,252.22 388.11,252.22 387.71,252.63 387.71,254.25 383.64,258.32 377.95,258.32 v362.92,273.36 | v312.93,246.94 312.12,246.94 310.08,248.97 299.92,248.97 267.82,281.08 267.82,281.48 267.41,281.89 266.6,281.89 262.13,277.42 258.88,280.67 256.85,280.67 v256.44,281.08
  Bottom 0.203: v95.91,116.48 91.85,112.42 86.56,112.42 85.75,111.61 85.75,110.79 83.31,110.79 81.69,109.17 66.65,109.17 65.84,108.36 C31.L2
AC06\  (via drill 0.61)
  Top 0.203: v413.31,205.08 414.12,204.27 414.12,200.61 AB04.BB1
  Route2 0.203: v284.89,176.22 284.48,175.82 284.48,172.16 B14.M2 | v343.81,176.22 343.81,176.63 372.67,205.49 v373.07,205.49
  Route15 0.203: B01.J2 445.41,181.1 444.19,181.1 442.57,182.73 440.94,182.73 431.6,192.07 424.28,192.07 418.19,198.17 416.56,198.17 414.93,199.8 AB04.BB1
  Bottom 0.203: v343.81,176.22 v284.89,176.22 | v373.07,205.49 397.05,205.49 397.46,205.08 v413.31,205.08
AC07  (via drill 0.61)
  Top 0.203: C31.M2 68.68,105.51 68.68,109.58 72.75,113.64 72.75,114.86 70.31,117.3 70.31,121.36 76,127.05 76,191.26 75.59,191.67 75.59,192.48 76,192.89 76,222.96 73.15,225.81 73.15,253.03 v69.49,256.69 69.49,257.1 69.49,274.17 v69.9,274.57 | v412.9,241.66 412.9,220.93 414.12,219.71 AB04.AV1
  Route2 0.203: v386.89,268.07 382.83,268.07 370.64,255.88 366.57,255.88 v364.95,254.25 | v319.02,279.45 317.81,279.45 313.33,274.98 308.05,274.98 304.39,271.32 291.8,271.32 279.2,258.72 273.91,258.72 v259.28,244.09
  Route15 0.203: D27.E2 118.67,54.71 118.67,57.96 114.2,62.43 112.57,62.43 96.72,78.28 95.91,78.28 95.1,79.1 91.03,79.1 81.28,88.85 81.28,89.66 70.31,100.63 70.31,102.67 68.68,104.29 C31.M2 | v412.9,241.66 412.9,242.47 387.3,268.07 v386.89,268.07 | v364.95,254.25 362.92,254.25 360.48,256.69 360.48,258.32 356.41,262.38 354.79,262.38 351.94,265.23 345.03,265.23 338.94,271.32 334.87,271.32 333.65,272.54 332.03,272.54 329.59,274.98 323.49,274.98 v319.02,279.45 | v259.28,244.09 256.44,241.25 v221.08,276.61
  Bottom 0.203: v69.49,256.69 66.24,256.69 65.84,257.1 AB31.AF2 | v221.08,276.61 175.16,276.61 174.75,276.2 156.46,276.2 155.25,274.98 103.23,274.98 102.41,274.17 101.6,274.17 100.79,274.98 70.31,274.98 v69.9,274.57
AC07\  (via drill 0.61)
  Top 0.203: v279.6,179.48 279.6,173.79 280.01,173.38 280.01,169.72 280.82,168.91 B14.N2 | v408.43,205.89 408.43,218.49 AB04.AV2
  Route15 0.203: B01.K2 448.67,178.26 447.45,179.48 445.01,179.48 442.16,182.32 440.54,182.32 436.88,185.98 v436.47,185.98 436.47,186.38 431.19,191.67 423.88,191.67 423.06,192.48 419.81,192.48 408.43,203.86 v408.43,205.89
  Bottom 0.203: v279.6,179.48 279.6,182.73 334.87,182.73 335.69,181.91 336.91,181.91 337.72,182.73 367.39,182.73 368.61,183.95 368.61,191.67 376.33,191.67 379.17,188.82 385.27,188.82 388.11,185.98 v436.47,185.98
AC08  (via drill 0.61)
  Top 0.203: v115.42,84.38 117.04,84.38 117.04,43.33 118.67,41.71 D27.K2 | v128.42,207.52 130.45,205.49 130.45,132.33 130.86,131.93 130.86,131.12 130.05,130.3 130.05,124.21 v129.24,123.39 | v386.08,263.2 382.42,266.85 382.42,268.48 377.55,268.48 377.55,270.51 373.48,274.57 370.64,274.57 v370.64,273.36 | v270.66,279.86 268.22,277.42 268.22,271.73 267,270.51 267,270.1 264.97,268.07 263.75,268.07 263.75,264.82 v264.16,264.41 | v230.84,261.98 225.96,257.1 v225.96,256.29
  Route2 0.203: v129.24,123.39 117.86,112.01 117.86,107.54 v98.75,88.44 | v370.64,273.36 344.22,246.94 343.41,246.94 v335.28,238.81
  Route15 0.203: v128.42,207.52 121.92,214.02 121.92,216.05 78.03,259.94 75.18,259.94 AB31.AE1 | v386.08,263.2 411.28,238 411.28,236.78 416.15,231.9 416.15,227.43 429.97,213.61 429.97,203.86 AB03.BA1 | v335.28,238.81 333.25,238.81 324.31,247.75 323.9,247.75 322.68,248.97 319.02,248.97 315.77,252.22 314.15,252.22 307.64,258.72 305.61,258.72 305.21,259.13 293.83,259.13 278.38,274.57 276.76,274.57 274.73,276.61 273.91,276.61 v270.66,279.86
  Bottom 0.203: 98.75,84.38 v115.42,84.38 | 98.75,84.38 69.49,84.38 68.68,85.19 C31.U2 | v98.75,88.44 98.75,84.38 | v264.16,264.41 263.75,264.82 254,264.82 251.56,262.38 246.69,262.38 246.28,261.98 v230.84,261.98 | v225.96,256.29 225.55,255.88 143.46,255.88 142.65,255.07 138.99,255.07 135.33,258.72 76.4,258.72 75.18,259.94 AB31.AE1
AC08\  (via drill 0.61)
  Top 0.203: v304.39,122.17 304.8,121.77 304.8,112.42 304.39,112.01 304.39,106.32 303.58,105.51 C13.M1 | v362.51,138.84 364.13,140.46 v364.13,146.15 | v426.31,153.87 425.91,154.28 425.91,198.58 426.72,199.39 AB03.BB1
  Route2 0.203: v320.65,138.43 v304.39,122.17
  Bottom 0.203: v320.65,138.43 321.06,138.84 336.5,138.84 337.31,138.02 346.25,138.02 347.07,138.84 v362.51,138.84 | v364.13,146.15 364.54,146.56 394.61,146.56 395.02,146.15 421.84,146.15 426.72,151.03 | 426.72,151.03 431.6,151.03 434.04,153.47 435.66,153.47 436.07,153.87 439.32,153.87 442.16,151.03 443.38,151.03 444.19,151.84 448.67,151.84 B01.U2 | v426.31,153.87 426.31,151.03 426.72,151.03
AC09  (via drill 0.61)
  Top 0.203: C31.S2 67.87,92.51 67.06,93.32 67.06,203.86 67.46,204.27 67.46,219.71 69.49,221.74 69.49,254.66 68.68,255.47 68.68,259.13 68.28,259.54 AB31.AE2 68.28,261.16 67.06,262.38 67.06,269.7 v68.28,270.92 | v412.09,237.19 410.06,239.22 410.06,240.44 409.65,240.84 409.65,250.6 412.5,253.44 412.5,269.7 409.25,272.95 v409.25,276.2
  Route2 0.203: v409.25,276.2 400.71,284.73 231.65,284.73 224.74,277.83 221.08,277.83 v213.77,270.51
  Route15 0.203: C31.S2 68.68,91.69 70.71,91.69 76,86.41 76,85.19 76.4,84.78 76.4,81.94 115.82,42.52 115.82,38.86 D27.L2 | v412.09,237.19 421.03,228.24 421.03,227.43 426.72,221.74 426.72,219.71 AB03.AV1
  Bottom 0.203: v213.77,270.51 212.95,271.32 170.28,271.32 167.03,268.07 136.96,268.07 136.55,267.67 132.89,267.67 132.08,268.48 89.41,268.48 86.97,270.92 85.34,270.92 84.94,271.32 76,271.32 75.59,270.92 72.34,270.92 71.93,271.32 68.68,271.32 v68.28,270.92
AC09\  (via drill 0.61)
  Top 0.203: v301.14,109.17 301.55,108.76 301.55,107.54 301.14,107.14 301.14,103.07 300.33,102.26 C13.N1 | v421.84,145.34 421.84,217.68 421.03,218.49 AB03.AV2
  Route2 0.203: v385.67,145.34 v348.69,108.36
  Bottom 0.203: v301.14,109.17 301.55,109.58 320.65,109.58 323.49,106.73 345.85,106.73 347.47,108.36 v348.69,108.36 | v385.67,145.34 386.08,145.75 421.84,145.75 | 421.84,145.75 427.94,145.75 432.82,150.62 436.47,150.62 439.32,147.78 444.19,147.78 445.41,149 B01.V2 | 421.84,145.75 v421.84,145.34
AC10  (via drill 0.61)
  Top 0.203: v108.92,46.99 110.95,44.96 110.95,32.36 115.42,27.89 115.42,25.86 D27.R2 116.23,24.64 117.04,23.83 117.04,18.14 106.88,7.98 106.88,2.69 288.54,2.69 v293.83,7.98 | v134.52,261.57 136.96,259.13 v136.96,159.97 | v422.66,148.59 422.66,105.92 v420.22,103.48 | v349.91,53.9 348.29,52.27 v348.29,51.87
  Route2 0.203: v136.96,159.97 136.96,159.56 127.2,149.81 127.2,149 69.09,90.88 67.46,90.88 65.84,89.26 C31.T2 | v422.66,148.59 431.6,157.53 431.6,197.36 432.82,198.58 434.04,198.58 438.51,203.05 442.16,203.05 AB02.BA1 | v402.74,104.7 398.68,100.63 398.68,100.23 398.27,99.82 397.87,99.82 390.96,92.91 390.96,88.85 376.73,74.62 372.67,74.62 352.75,54.71 350.72,54.71 v349.91,53.9 | v348.29,51.87 347.47,51.87 321.46,25.86 321.06,25.86 320.24,25.04 320.24,24.64 306.83,11.23 305.21,11.23 303.99,10.01 295.86,10.01 v293.83,7.98
  Route15 0.203: v108.92,46.99 97.54,58.37 97.54,59.18 67.87,88.85 65.84,88.85 C31.T2
  Bottom 0.203: v134.52,261.57 100.79,261.57 97.54,264.82 72.75,264.82 71.93,264.01 AB31.AD1 | v420.22,103.48 419.81,103.07 404.37,103.07 403.96,102.67 403.15,102.67 402.74,103.07 v402.74,104.7
AC10\  (via drill 0.61)
  Top 0.203: v438.51,147.37 438.51,198.58 439.32,199.39 AB02.BB1
  Route2 0.203: v338.12,59.18 347.07,68.12 349.91,68.12 360.88,79.1 361.7,79.1 363.73,81.13 364.13,81.13 366.57,83.57 366.57,83.97 366.98,84.38 367.39,84.38 373.07,90.07 v373.07,90.47 | v434.04,86 434.85,86 445.82,96.98 446.23,96.98 446.63,97.38 446.63,99.01 451.51,103.89 451.51,105.1 453.95,107.54 453.95,111.2 454.36,111.61 454.36,114.86 455.17,115.67 455.17,116.89 C01.H1
  Route15 0.203: v338.12,59.18 338.12,59.59 315.77,81.94 315.77,82.35 303.17,94.94 303.17,97.79 C13.P1 | v373.07,90.47 376.73,90.47 v379.58,87.63
  Bottom 0.203: v379.58,87.63 379.98,87.22 399.08,87.22 401.52,84.78 403.96,84.78 404.37,84.38 407.62,84.38 410.87,87.63 423.06,87.63 423.47,87.22 431.6,87.22 432.82,86 v434.04,86 | v438.51,147.37 442.98,142.9 453.95,142.9 454.36,142.49 454.36,118.11 455.17,118.11 C01.H1
AC11  (via drill 0.61)
  Top 0.203: v67.87,232.72 67.87,233.12 67.06,233.93 67.06,261.16 65.43,262.79 AB31.AD2 | v79.65,220.93 79.65,155.91 82.09,153.47 v82.09,89.26 | v115.01,41.71 117.86,38.86 117.86,24.23 119.08,23.01 D27.S2 | v351.94,204.67 v351.94,214.02 | v314.55,180.7 314.55,153.47 311.3,150.22 311.3,145.34 v311.71,144.93
  Route2 0.203: v330.4,203.05 330.4,202.23 321.06,192.89 321.06,187.2 v314.55,180.7 | v267,145.34 267,144.93 260.91,138.84 257.25,138.84 218.64,100.23 205.64,100.23 154.84,49.43 148.34,49.43 132.49,33.58 121.92,33.58 116.23,27.89 116.23,27.08 119.89,23.42 119.08,22.61 D27.S2
  Route15 0.203: v79.65,220.93 v67.87,232.72 | v115.01,41.71 115.01,42.11 97.94,59.18 97.94,59.59 76,81.53 76,84.38 75.18,85.19 C31.U1
  Bottom 0.203: v82.09,89.26 78.84,86 75.18,86 C31.U1 | v351.94,214.02 353.16,214.02 355.6,216.46 367.39,216.46 367.79,216.05 374.29,216.05 374.7,216.46 409.65,216.46 410.06,216.05 420.22,216.05 422.66,213.61 434.44,213.61 439.32,218.49 AB02.AV1 | v351.94,204.67 351.54,205.08 332.44,205.08 v330.4,203.05 | v311.71,144.93 299.52,144.93 299.11,144.53 290.58,144.53 290.17,144.93 267.41,144.93 v267,145.34
AC11\  (via drill 0.61)
  Top 0.203: v429.97,216.05 428.75,214.83 v428.75,127.46
  Route2 0.203: v343.41,136.8 343.41,136.4 337.72,130.71 337.72,128.27 337.31,127.86 336.91,127.86 327.15,118.11 327.15,116.89 325.93,115.67 324.71,115.67 311.3,102.26 311.3,101.85 310.49,101.04 310.08,101.04 305.21,96.16 305.21,95.76 304.39,94.94 300.74,94.94 C13.R1 | v429.97,216.05 432.41,218.49 432.82,218.49 AB02.AV2
  Route15 0.203: v359.66,138.02 360.88,138.02 v375.92,122.99
  Bottom 0.203: v343.41,136.8 344.22,137.62 346.66,137.62 347.07,138.02 348.29,138.02 349.1,137.21 350.72,137.21 351.54,138.02 v359.66,138.02 | v375.92,122.99 376.33,122.58 428.75,122.58 | 428.75,122.58 447.04,122.58 448.67,120.95 451.92,120.95 C01.F1 | 428.75,122.58 v428.75,127.46
AC\_ENABLE  (via drill 0.61)
  Top 0.203: v377.55,232.72 377.95,232.31 377.95,214.43 377.55,214.02 v377.55,181.91
  Route15 0.203: v377.55,232.72 366.17,244.09 364.13,244.09 A08.L1
  Bottom 0.203: 405.99,182.32 401.12,182.32 400.71,181.91 396.24,181.91 395.83,181.51 AB05.BJ2 394.61,181.1 393.8,181.91 390.14,181.91 389.74,182.32 386.89,182.32 385.67,181.1 383.24,181.1 AB06.BJ2 382.02,181.51 381.2,182.32 377.55,182.32 | 405.99,182.32 407.21,181.1 AB04.BJ2 | 419.4,182.32 420.22,181.51 AB03.BJ2 | 405.99,182.32 419.4,182.32 | 419.4,182.32 432,182.32 432.82,181.51 AB02.BJ2 | 377.55,182.32 371.86,182.32 370.64,181.1 AB07.BJ2 | 377.55,182.32 v377.55,181.91
AC_CLEAR  (via drill 0.61)
  Top 0.203: v271.48,57.96 272.69,56.74 v272.69,51.87
  Route15 0.203: v103.63,222.96 111.76,214.83 112.17,214.83 123.95,203.05 123.95,202.64 178.82,147.78 180.85,147.78 241.81,86.82 242.21,86.82 271.07,57.96 v271.48,57.96
  Bottom 0.203: v103.63,222.96 96.72,229.87 92.66,229.87 90.22,227.43 86.56,227.43 84.12,229.87 51.21,229.87 49.99,228.65 A33.S1 | v272.69,51.87 273.1,52.27 283.67,52.27 286.51,49.43 298.7,49.43 299.52,50.24 D13.F1
AC_CLEAR\  (via drill 0.61)
  Route2 0.203: v304.8,40.49 305.61,41.3 303.58,43.33 303.58,46.99 D13.H1
  Bottom 0.203: v304.8,40.49 305.21,40.08 346.25,40.08 347.07,40.89 D09.K2
AC_ENABLE  (via drill 0.61)
  Top 0.203: v352.75,208.33 352.35,208.74 352.35,213.21 352.75,213.61 352.75,242.06 351.13,243.69 A09.L1
  Route15 0.203: v352.75,208.33 351.13,206.7 352.75,205.08 352.75,202.23 369.01,185.98 370.64,185.98 372.26,184.35 AB07.BH2
  Bottom 0.203: 409.25,185.57 400.3,185.57 399.08,184.35 AB05.BH2 397.87,184.35 396.65,185.57 390.14,185.57 388.93,184.35 386.49,184.35 AB06.BH2 385.27,183.54 384.45,182.73 374.29,182.73 373.48,183.54 AB07.BH2 | 409.25,185.57 410.46,184.35 AB04.BH2 | 421.84,185.57 423.06,184.35 AB03.BH2 | 409.25,185.57 421.84,185.57 | 421.84,185.57 435.25,185.57 436.07,184.76 AB02.BH2
AC_LOAD  (via drill 0.61)
  Top 0.203: v319.43,170.94 319.43,174.19 B11.L2 | v321.06,169.32 321.06,147.37 v321.46,146.96 | v357.23,146.56 357.23,148.59 B08.V2 | v380.39,179.07 380.8,179.48 380.8,203.86 379.58,205.08 379.58,221.74 AB07.AU1
  Route2 0.203: v321.06,169.32 v319.43,170.94 | v380.39,179.07 382.42,177.04 377.14,171.75 376.73,171.75 364.95,159.97 364.95,159.16 358.85,153.06 358.85,151.03 357.63,149.81 B08.V2
  Bottom 0.203: AB07.AU1 379.98,221.74 380.8,220.93 390.14,220.93 391.36,222.15 AB06.AU1 392.58,221.74 393.39,220.93 401.12,220.93 402.34,222.15 404.37,222.15 AB05.AU1 405.59,222.15 406.81,220.93 412.09,220.93 412.9,221.74 416.97,221.74 AB04.AU1 418.19,222.15 419.4,220.93 428.75,220.93 429.56,221.74 AB03.AU1 430.78,221.74 435.25,221.74 436.07,220.93 437.29,220.93 437.69,221.34 441.35,221.34 442.16,222.15 AB02.AU1 | v321.46,146.96 323.09,145.34 348.69,145.34 349.5,146.15 356.82,146.15 v357.23,146.56
ADD\  (via drill 0.61)
  Top 0.203: v390.96,176.63 390.55,177.04 390.55,202.23 387.71,205.08 v387.71,209.96 | v365.35,232.31 364.95,232.72 364.95,247.34 v364.54,247.75
  Route2 0.203: v301.95,146.96 301.95,147.37 302.77,148.18 302.77,149.4 305.21,151.84 306.43,151.84 v312.52,157.94 | v337.31,134.77 337.72,134.77 340.97,138.02 342.19,138.02 v380.39,176.22
  Route15 0.203: v301.95,146.96 304.8,144.12 304.8,142.49 308.05,139.24 308.05,135.99 312.12,131.93 312.12,127.46 C12.D1 | v312.52,157.94 320.24,150.22 320.24,149.4 334.47,135.18 336.91,135.18 v337.31,134.77 | v387.71,209.96 383.64,214.02 383.64,214.43 365.76,232.31 v365.35,232.31
  Bottom 0.203: v380.39,176.22 380.8,176.63 v390.96,176.63 | v364.54,247.75 360.88,247.75 A08.K2 359.66,247.34 354.79,247.34 A09.K1
ADD_ACCEPTED\  (via drill 0.61)
  Route2 0.203: v297.49,12.04 303.17,17.73 307.24,17.73 333.65,44.15 333.65,48.21 339.34,53.9 340.56,53.9 D10.E1
  Route15 0.203: v204.83,9.6 188.98,25.45 187.35,25.45 186.13,26.67 180.85,26.67 148.74,58.78 148.74,60.4 117.86,91.29 117.86,92.91 116.23,94.54 C27.R2
  Bottom 0.203: v297.49,12.04 296.67,11.23 231.65,11.23 230.02,9.6 v204.83,9.6
ADDER00  (via drill 0.61)
  Top 0.203: v373.07,264.82 373.07,261.16 AB07.AE2 | v428.75,265.23 432,261.98 432,252.22 432.82,251.41 AB02.AJ2
  Route2 0.203: v369.42,207.92 341.78,180.29 341.78,178.26 B10.K1 | v392.18,214.43 392.58,214.43 428.35,250.19 v428.75,250.19
  Bottom 0.203: v373.07,264.82 373.48,265.23 382.42,265.23 383.64,266.45 | 383.64,266.45 386.49,269.29 388.52,269.29 AB06.AB1 | v369.42,207.92 375.11,213.61 381.2,213.61 382.02,214.43 v392.18,214.43 | v428.75,250.19 429.16,250.6 432.82,250.6 AB02.AJ2 | 383.64,266.45 384.86,265.23 404.77,265.23 405.59,264.41 406.81,264.41 407.21,264.82 412.09,264.82 412.5,265.23 v428.75,265.23
ADDER01  (via drill 0.61)
  Top 0.203: v374.29,207.92 375.11,208.74 375.11,255.88 375.92,256.69 AB07.AF1
  Route2 0.203: v374.29,207.92 341.38,175.01 341.38,172.16 B10.M1 | AB06.AC1 391.36,266.45 387.71,266.45 380.39,259.13 378.36,259.13 376.73,257.5 AB07.AF1
ADDER02
  Route2 0.203: AB05.AB1 401.12,269.29 396.65,269.29 389.74,262.38 388.11,262.38 386.49,260.76 AB06.AE2
  Bottom 0.203: AB07.AH2 372.26,254.25 370.64,255.88 369.42,255.88 368.61,256.69 368.61,259.13 384.45,259.13 385.27,259.94 AB06.AE2
ADDER03  (via drill 0.61)
  Top 0.203: v388.52,253.03 388.52,256.69 AB06.AF1 389.33,257.91 390.14,258.72 390.14,274.57 405.18,274.57 405.99,273.76 405.99,268.07 405.18,267.26 AB05.AC1
  Bottom 0.203: v388.52,253.03 387.71,252.22 375.51,252.22 374.29,251 370.64,251 AB07.AJ2
ADDER04  (via drill 0.61)
  Top 0.203: v386.89,259.13 386.89,255.47 386.08,254.66 AB06.AH2
  Route2 0.203: AB04.AB1 413.71,269.7 411.68,269.7 406.4,264.41 404.37,264.41 402.34,262.38 400.71,262.38 399.08,260.76 AB05.AE2
  Bottom 0.203: v386.89,259.13 397.05,259.13 397.87,259.94 AB05.AE2
ADDER05  (via drill 0.61)
  Top 0.203: v405.99,265.23 401.93,261.16 401.93,257.91 AB05.AF1
  Route2 0.203: v384.45,255.88 382.83,254.25 382.83,251.41 AB06.AJ2
  Bottom 0.203: v384.45,255.88 400.3,255.88 401.12,256.69 AB05.AF1 | v405.99,265.23 411.68,265.23 412.09,265.63 416.15,265.63 416.97,266.45 AB04.AC1
ADDER06  (via drill 0.61)
  Top 0.203: v398.68,258.72 398.68,254.66 AB05.AH2
  Route2 0.203: AB03.AB1 426.31,269.7 422.66,269.7 415.34,262.38 413.31,262.38 411.68,260.76 AB04.AE2
  Bottom 0.203: v398.68,258.72 399.08,259.13 409.65,259.13 410.46,259.94 AB04.AE2
ADDER07  (via drill 0.61)
  Top 0.203: v413.31,252.22 413.71,252.63 413.71,256.69 AB04.AF1
  Route2 0.203: AB03.AC1 429.56,266.45 425.5,266.45 418.19,259.13 416.56,259.13 414.93,257.5 AB04.AF1
  Bottom 0.203: v413.31,252.22 396.65,252.22 395.83,251.41 AB05.AJ2
ADDER08
  Top 0.203: AB02.AB1 439.32,270.51 437.69,272.14 437.69,273.76 432.82,278.64 424.69,278.64 424.69,274.17 425.09,273.76 425.09,262.38 423.88,261.16 AB03.AE2
  Route2 0.203: AB04.AH2 411.68,254.25 415.75,254.25 419.81,258.32 421.03,258.32 423.06,260.35 AB03.AE2
ADDER09  (via drill 0.61)
  Route2 0.203: v408.84,255.47 408.43,255.07 408.43,251.41 AB04.AJ2
  Bottom 0.203: v408.84,255.47 409.25,255.88 423.47,255.88 424.69,257.1 426.31,257.1 AB03.AF1 427.53,256.69 428.35,255.88 434.04,255.88 436.47,258.32 444.19,258.32 444.19,260.76 443.38,261.57 443.38,266.04 AB02.AC1
ADDER10  (via drill 0.61)
  Top 0.203: v423.88,258.72 423.88,254.66 AB03.AH2
  Route2 0.203: v359.26,205.89 344.22,190.86 341.78,190.86 B10.E1 | v389.33,213.21 389.33,216.05 421.44,248.16 421.44,249.38 421.84,249.78 421.84,251.82 423.47,253.44 AB03.AH2
  Bottom 0.203: v359.26,205.89 359.66,206.3 387.3,206.3 392.99,211.99 392.99,213.21 v389.33,213.21 | v423.88,258.72 434.85,258.72 436.07,259.94 AB02.AE2
ADDER11  (via drill 0.61)
  Top 0.203: v338.53,213.61 338.94,213.21 338.94,201.02 338.53,200.61 B10.B1 | v373.89,216.86 374.29,217.27 374.29,249.38 | 374.29,249.38 374.29,267.67 375.92,269.29 AB07.AB1 | 374.29,249.38 v373.89,249.38
  Route15 0.203: v338.53,213.61 v341.78,216.86
  Bottom 0.203: AB02.AF1 440.13,256.69 444.19,256.69 444.19,253.44 443.38,252.63 438.1,252.63 437.69,252.22 422.66,252.22 421.44,251 AB03.AJ2 420.22,250.19 419.4,249.38 v373.89,249.38 | v341.78,216.86 342.19,216.46 353.16,216.46 353.57,216.86 v373.89,216.86
ADDER_L\  (via drill 0.61)
  Top 0.203: v335.69,154.28 336.09,154.69 v336.09,182.73 336.09,183.13 336.5,183.54 336.5,192.89 v336.09,193.29 | AB07.AC1 379.58,266.04 381.2,264.41 v381.2,255.07 381.2,254.66 381.2,248.16 384.05,245.31 384.05,214.02 382.83,212.8 382.83,203.86 384.05,202.64 384.05,196.95 v382.42,195.33
  Route2 0.203: v335.69,154.28 335.28,153.87 334.47,153.87 333.65,153.06 333.65,152.65 332.03,151.03 332.03,149.81 B10.V2
  Bottom 0.203: v336.09,182.73 337.31,183.95 340.56,183.95 B10.H1 | v381.2,255.07 384.86,255.07 385.27,255.47 407.62,255.47 408.43,254.66 409.65,254.66 410.46,255.47 435.25,255.47 436.07,254.66 AB02.AH2 | v336.09,193.29 337.72,194.92 382.02,194.92 v382.42,195.33
AND  (via drill 0.61)
  Top 0.203: v387.71,191.67 v387.71,125.83
  Route15 0.203: v344.22,236.37 356.41,224.18 356.82,224.18 359.26,221.74 359.26,221.34 365.76,214.83 366.17,214.83 367.79,213.21 367.79,211.99 387.71,192.07 v387.71,191.67
  Bottom 0.203: v344.22,236.37 343.81,236.78 334.87,236.78 333.25,235.15 329.18,235.15 A11.P1 | v387.71,125.83 386.89,125.02 383.64,125.02 382.83,124.21 379.98,124.21 C07.E1
AND\  (via drill 0.61)
  Route2 0.203: v319.02,116.48 306.83,104.29 306.83,102.26 C12.N2 | v359.66,125.83 358.85,125.83 357.63,124.61 356.82,124.61 351.54,119.33 349.91,119.33 348.29,117.7 C09.H2
  Bottom 0.203: v319.02,116.48 319.43,116.08 337.72,116.08 340.56,118.92 343,118.92 344.22,117.7 347.07,117.7 C09.H2 | v359.66,125.83 374.7,125.83 375.51,126.64 C07.D1
AND_ENABLE  (via drill 0.61)
  Top 0.203: v386.49,200.61 386.89,201.02 v386.89,219.3 | v400.3,232.72 400.3,266.45 401.52,267.67 | 401.52,267.67 404.37,270.51 404.37,272.54 AB05.AA1 | 401.52,267.67 397.05,272.14 397.05,272.54 392.58,272.54 AB06.AA1
  Route2 0.203: v386.49,200.61 363.73,177.85 363.73,175.41 B08.L1 | v386.89,219.3 v400.3,232.72
  Bottom 0.203: 428.75,271.73 419.4,271.73 418.19,272.95 AB04.AA1 416.97,272.54 416.15,271.73 406.81,271.73 405.59,272.95 AB05.AA1 | 428.75,271.73 429.56,272.54 AB03.AA1 | 428.75,271.73 440.94,271.73 442.16,272.95 AB02.AA1 | AB07.AA1 379.98,272.54 380.8,271.73 390.14,271.73 391.36,272.95 AB06.AA1
AND_ENABLE\  (via drill 0.61)
  Top 0.203: v349.5,240.03 349.5,255.88 350.32,256.69 A09.F1 | B08.H1 366.17,183.54 366.17,178.26 B08.K1
  Route2 0.203: v329.18,219.71 v349.5,240.03
  Route15 0.203: A11.U1 329.18,221.74 v329.18,219.71 329.18,217.27 361.7,184.76 361.7,182.73 362.92,181.51 B08.J1
  Bottom 0.203: B08.H1 366.17,184.76 364.13,186.79 B08.F1 | B08.K1 366.17,178.26 364.13,180.29 363.73,180.29 B08.J1
B
  Route2 0.203: C34.T2 27.23,89.66 27.23,93.32 33.33,99.42 33.33,99.82 33.73,100.23 34.14,100.23 69.49,135.59 69.49,136.8 70.31,137.62 70.31,139.65 79.25,148.59 79.25,150.62 80.47,151.84 AB30.BU2
B01V1  (via drill 0.61)
  Top 0.508: v110.95,281.48 110.95,235.56 106.88,235.56 A28A.P2 | v442.57,279.86 444.6,277.83 v444.6,151.03
  Bottom 0.508: v110.95,281.48 111.76,282.3 159.31,282.3 160.12,283.11 439.32,283.11 v442.57,279.86 | v444.6,151.03 445.01,150.62 451.1,150.62 451.92,149.81 B01.V1
B29B2
  Bottom 0.508: AB29.BB2 91.03,200.61 91.85,201.42 100.79,201.42 102.01,200.2 102.41,200.2 B28.B2
B\
  Route2 0.203: C34.S2 30.07,91.29 30.07,90.07 27.64,87.63 26.42,87.63 23.98,90.07 25.2,91.29 25.2,96.16 51.21,122.17 51.21,123.39 63.4,135.59 63.4,137.62 68.68,142.9 68.68,144.53 82.09,157.94 82.09,159.56 83.72,161.19 AB30.BR1
B_BK  (via drill 0.61)
  Top 0.203: v352.75,174.19 352.35,173.79 352.35,161.59 351.94,161.19 351.94,156.31 352.35,155.91 352.35,154.28 348.29,150.22 v346.66,150.22 | v342.6,147.78 340.97,146.15 340.97,138.02 340.16,137.21 340.16,109.58 v340.97,108.76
